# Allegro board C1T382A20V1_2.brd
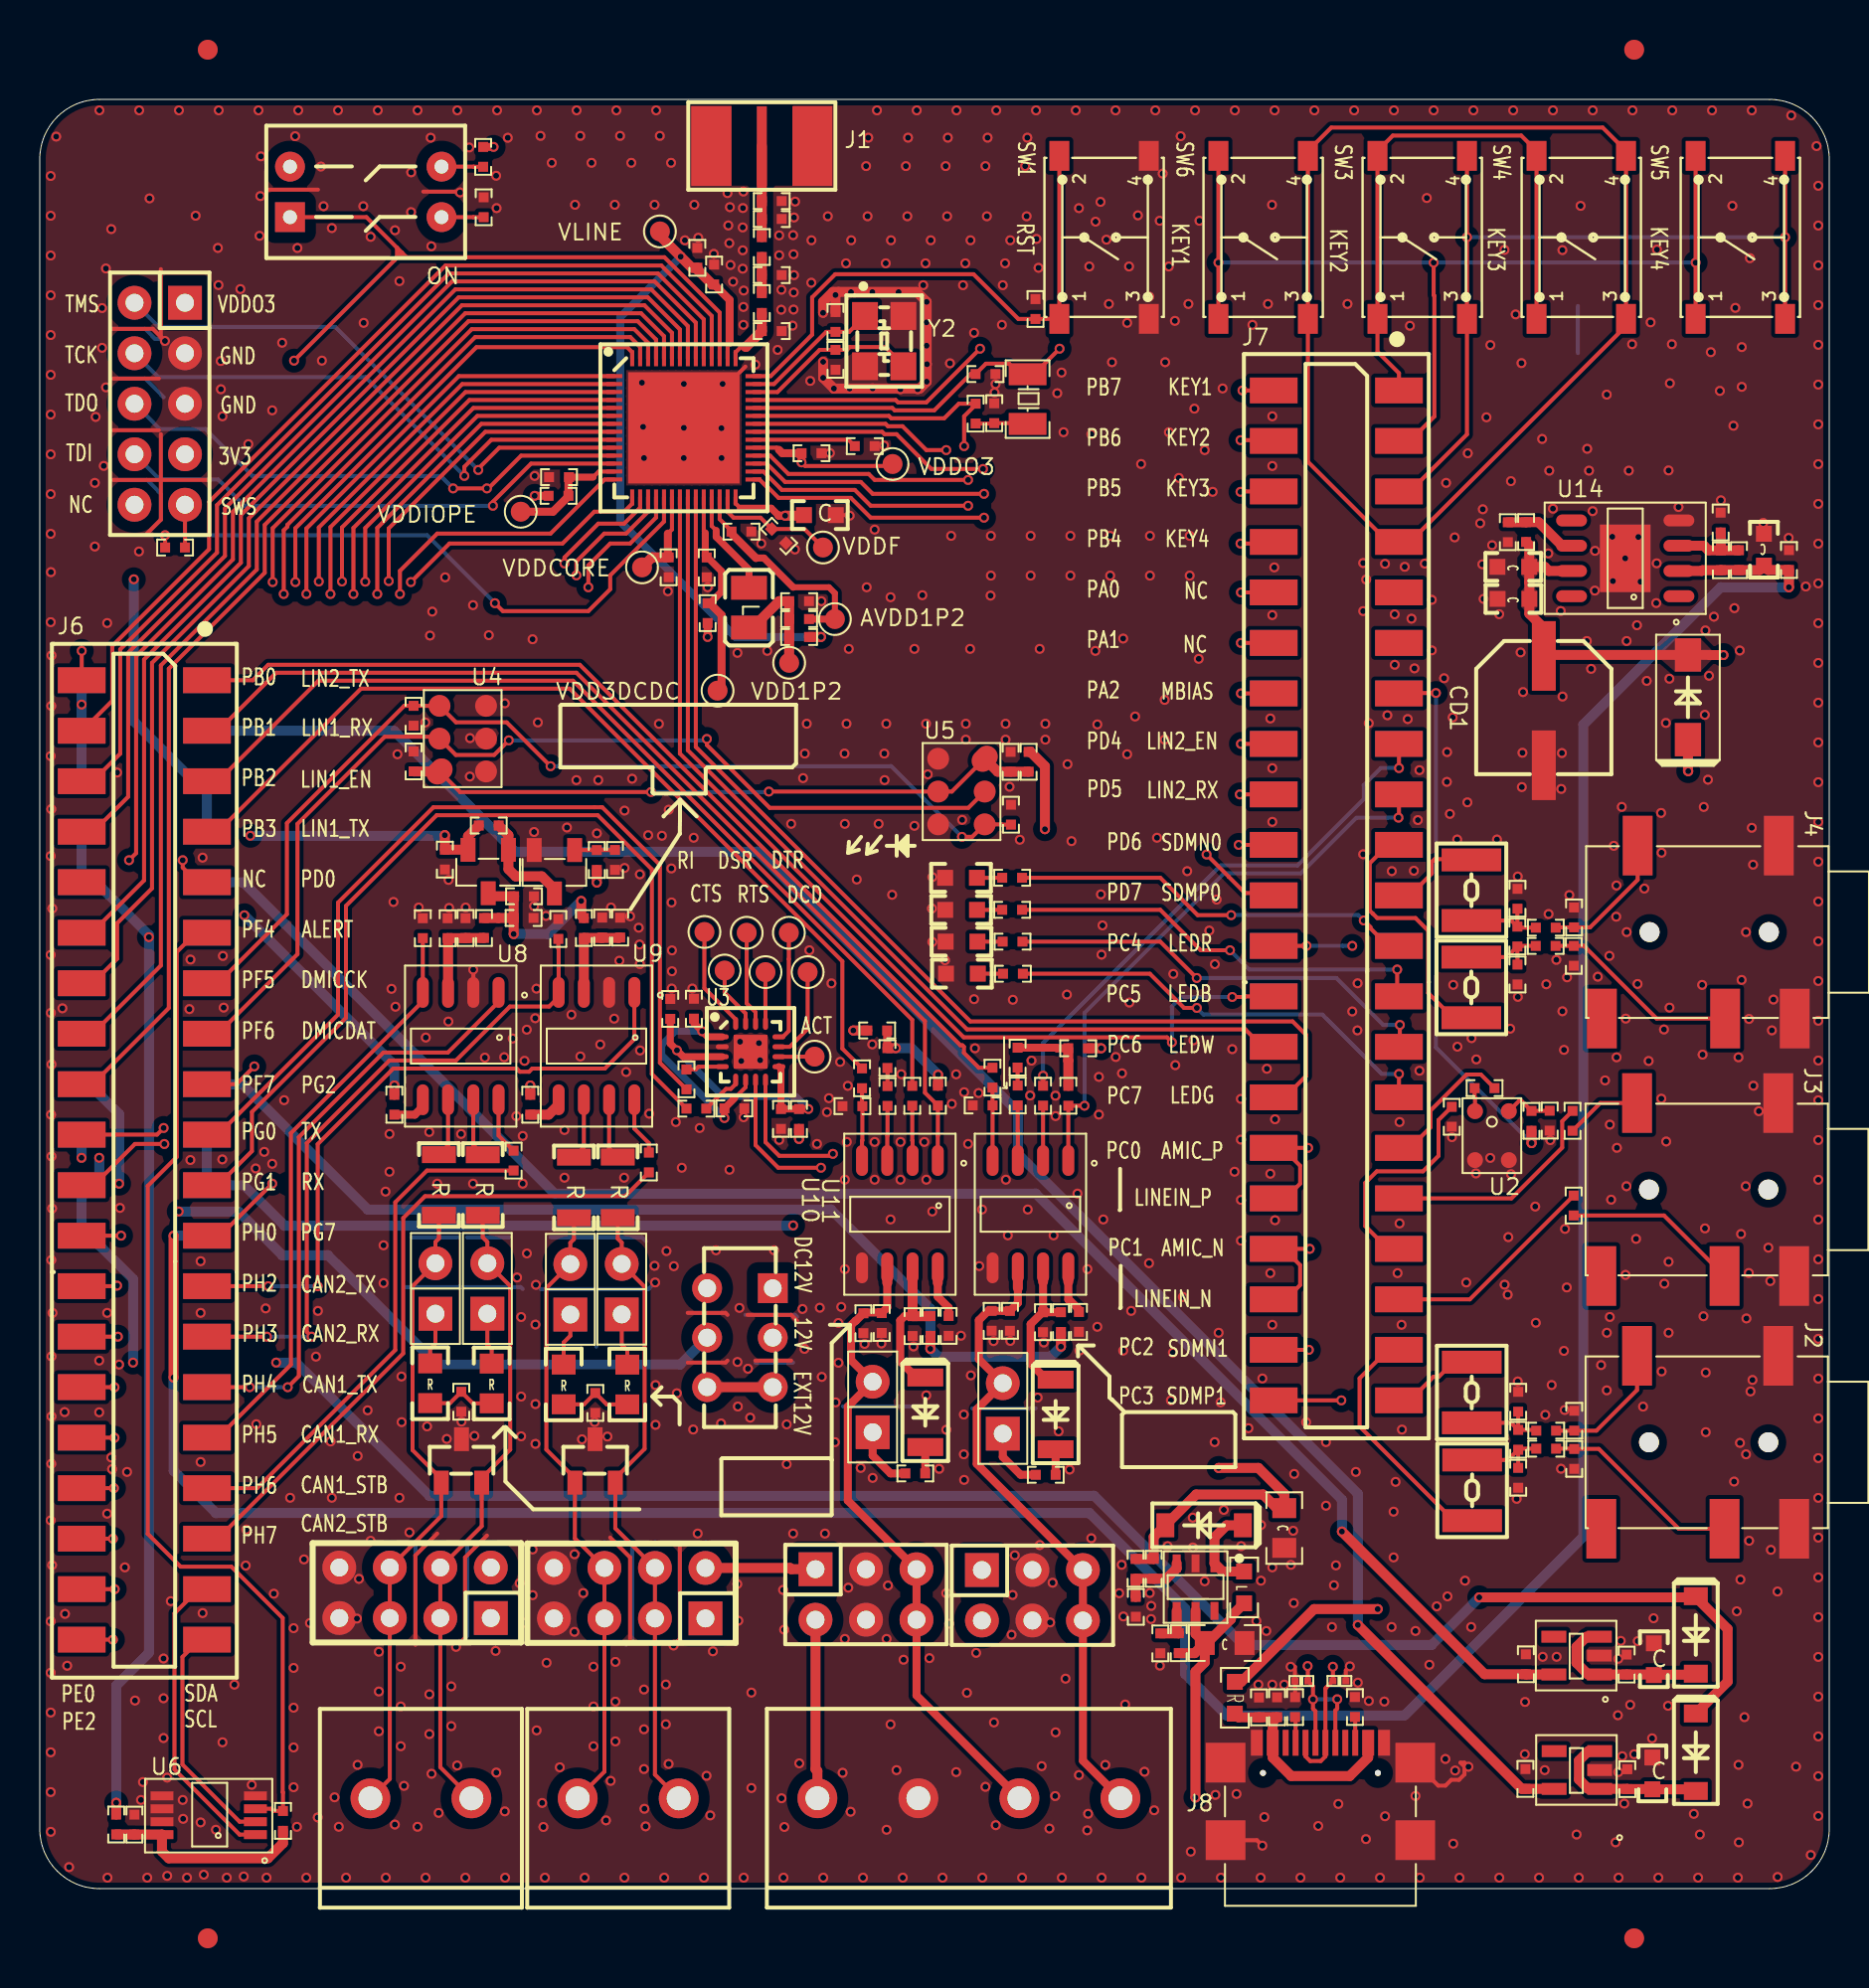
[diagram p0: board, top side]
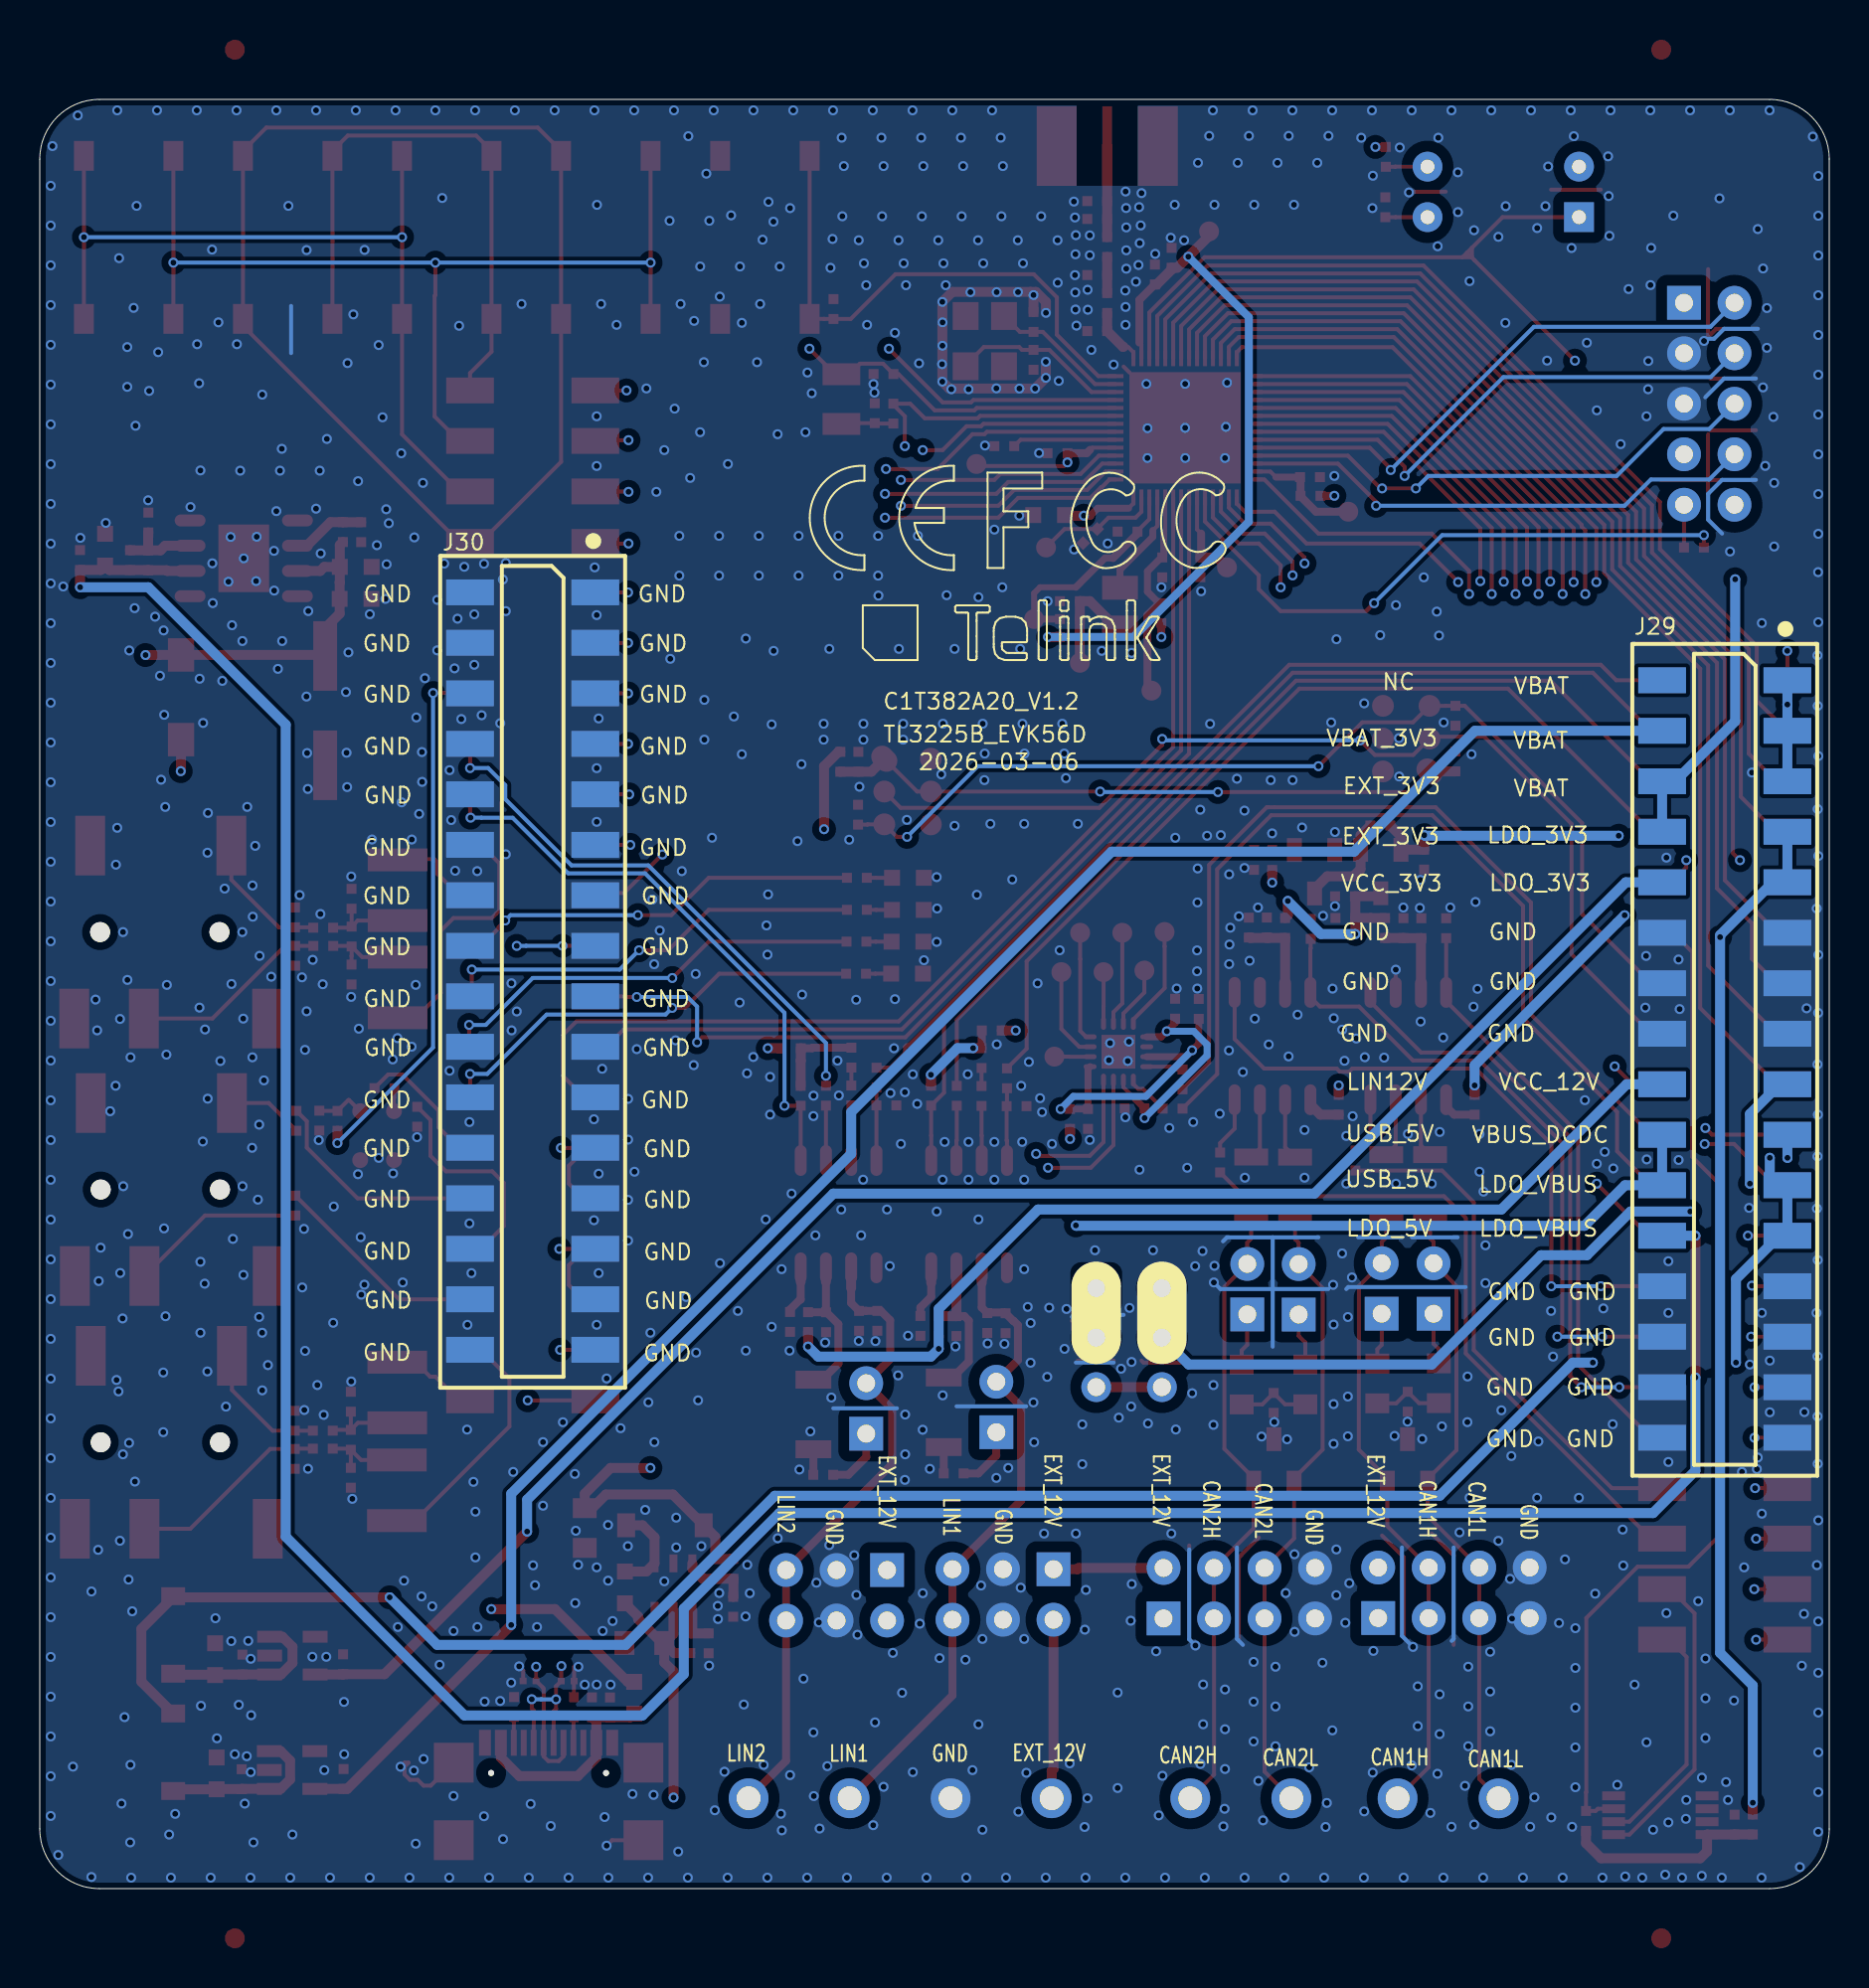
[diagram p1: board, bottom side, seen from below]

Outline 90 x 90 mm; copper layers: TOP, GND, POWER, BOTTOM. Coordinates in mm from the lower left corner of the outline.
Outline path: 0,87 arc(0.88,89.12) 3,90 87,90 arc(89.12,89.12) 90,87 90,3 arc(89.12,0.88) 87,0 3,0 arc(0.88,0.88) 0,3 0,87

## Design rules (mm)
constraint set DEFAULT: 

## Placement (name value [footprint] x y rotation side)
AVDD1P2  TP  [TP100]  39.99 63.86 0 top
C1  0.1uF  [0402]  33.92 81.19 90 top
C2  2.2uF  [0402]  33.07 82.03 90 top
C3  1.2pF  [0402]  36.81 78.35 0 top
C4  2.7pF  [0402]  36.81 81.16 0 top
C5  1.5pF  [0402]  36.81 83.98 0 top
C6  22pF  [0402]  47.56 76.19 180 top
C7  22pF  [0402]  48 74.22 270 top
C8  1uF  [0402]  50.08 79.45 90 top
C9  NC  [0402]  40.02 78.81 270 top
C10  1uF  [0402]  41.49 72.56 0 top
C11  NC  [0402]  40.02 76.9 270 top
C12  1uF  [0402]  38.81 72.2 0 top
C13  1uF  [0402]  26.12 71 180 top
C14  1uF  [0402]  37.17 68.04 315 top
C15  10uF  [0603C]  39.23 69.09 0 top
C16  4.7uF  [0402]  31.63 66.46 270 top
C17  1uF  [0402]  33.55 66.46 270 top
C18  1uF  [0402]  35.29 68.26 0 top
C19  NC  [0402]  74.36 20.67 90 top
C20  10pF  [0402]  77.17 21.62 90 top
C21  10nF  [0402]  72.67 40.27 0 top
C22  1uF  [0402]  75.94 38.63 270 top
C23  220nF  [0402]  74.36 22.57 90 top
C24  NC  [0402]  74.36 24.49 90 top
C25  10pF  [0402]  77.17 23.54 90 top
C26  1uF  [0402]  77.09 38.62 90 top
C27  NC  [0402]  74.32 45.98 90 top
C28  10pF  [0402]  77.16 46.92 90 top
C31  220nF  [0402]  74.32 47.89 90 top
C32  NC  [0402]  74.32 49.79 90 top
C33  10pF  [0402]  77.16 48.85 90 top
C35  0.1uF  [0402]  48.83 56.68 90 top
C36  0.1uF  [0402]  18.8 56.7 90 top
C37  0.1uF  [0402]  4.76 3.22 90 top
C38  0.1uF  [0402]  34.94 39.25 0 top
C39  4.7uF  [0402]  21.41 48.31 270 top
C40  0.1uF  [0402]  20.52 48.31 270 top
C43  NC  [0402]  19.27 48.31 270 top
C44  4.7uF  [0402]  29.19 48.34 270 top
C45  0.1uF  [0402]  28.28 48.34 270 top
C46  NC  [0402]  26.08 48.27 270 top
C47  4.7nF  [0402]  21.2 24.49 270 top
C48  10uF  [0402]  20.38 51.76 270 top
C49  10uF  [0402]  24.35 49.92 0 top
C50  4.7nF  [0402]  27.94 24.43 270 top
C51  0.1uF  [0402]  40.87 39.36 0 top
C52  100nF/25V  [0402]  43.89 28.3 90 top
C53  0.1uF  [0402]  47.42 39.39 0 top
C54  220pF  [0402]  48.79 28.56 90 top
C55  220pF  [0402]  42.34 28.45 90 top
C56  100nF/25V  [0402]  50.45 28.49 90 top
C57  NC  [0402]  56.02 16.09 270 top
C58  4.7uF/25V  [0805C]  62.59 18.14 270 top
C59  10uF  [0603C]  81.18 11.54 270 top
C60  1uF  [0402]  79.81 11.27 90 top
C61  1uF  [0402]  74.75 11.29 90 top
C62  4.7uF/25V  [0805C]  59.59 12.35 0 top
C63  1uF  [0402]  87.97 66.83 270 top
C64  4.7uF  [0603C]  86.72 67.35 90 top
C65  NC/1uF  [0402]  85.46 66.83 270 top
C66  4.7uF/25V  [0603C]  74.11 66.48 180 top
C67  10uF/25V  [0603C]  74.12 64.88 180 top
C68  1uF  [0402]  74.72 5.52 90 top
C69  10uF  [0603C]  81.11 5.79 270 top
C70  1uF  [0402]  79.84 5.51 90 top
C71  10uF  [0402]  61.32 9.12 90 top
C72  10uF  [0402]  38.19 64.76 0 top
C73  1uF  [0402]  77.14 34.36 90 top
C74  10nF  [0402]  71.02 38.83 90 top
C75  1uF  [0402]  37.28 38.72 270 top
C76  1uF  [0402]  32.9 44.26 90 top
C77  1uF  [0402]  31.71 44.25 90 top
CD1  100uF/35V  [VZH101M1VTR-0607]  75.64 59.25 90 top
D1  NC  [0201]  63.45 10.44 0 top
D2  NC  [0201]  65.36 10.45 180 top
D3  NC  [0402]  62.23 9.12 270 top
D4  Red  [0603-LED]  46.33 50.84 180 top
D5  Blue  [0603-LED]  46.34 49.23 180 top
D6  White  [0603-LED]  46.36 47.63 180 top
D7  Green  [0603-LED]  46.38 46.02 180 top
D8  PESD1CAN,215  [SOT-23]  21.21 21.51 0 top
D9  PESD1CAN,215  [SOT-23]  27.93 21.51 0 top
D10  4148  [SOD80]  44.54 23.96 270 top
D11  4148  [SOD80]  51.09 23.85 270 top
D12  NC  [0402]  41.42 28.44 90 top
D13  NC  [0402]  47.88 28.56 90 top
D14  LMBR0530T1G  [SOD-123]  58.56 18.27 0 top
D15  B340A  [DO-214AC]  82.89 59.92 270 top
D16  NC/TT0321  [0402]  36.81 84.88 180 top
D17  LMBR0530T1G  [SOD-123]  83.29 12.76 90 top
D18  LMBR0530T1G  [SOD-123]  83.29 6.86 90 top
J1  RFIN  [SMA-H]  36.31 87.66 270 top
J2  PJ327  [PJ-327]  89.94 22.45 270 top
J3  AIL1  [PJ-327]  89.94 35.16 270 top
J4  PJ327  [PJ-327]  89.97 48.11 270 top
J6  HEADER 20X2  [HDR2X20-2R54-SM-VM]  5.26 34.11 90 top
J7  HEADER 21x2  [HDR2X21-2R54-SM-M]  65.21 49.92 90 top
J8  Type-C 16pin  [TYPE_C_CQ_105PWB]  64.41 6.34 0 top
J9  JTAG  [HDR254F-2X5X850]  7.3 69.61 90 top
J10  DIP_2X2  [DIPSWITCH_2P54_7P62_2X2]  16.39 85.35 270 top
J15  CAN_Master_EN  [HDR254F-1X2X850]  22.51 31.46 270 top
J16  HEADER 4X2  [HDR254F-2X4X850]  12.52 13.61 0 top
J17  CON_5P08_1x2  [CON_5P08_1X2]  16.63 4.54 0 top
J18  CAN_Master_EN  [HDR254F-1X2X850]  19.9 31.46 270 top
J19  CAN_Master_EN  [HDR254F-1X2X850]  29.27 31.42 270 top
J20  HEADER 4X2  [HDR254F-2X4X850]  23.32 13.59 0 top
J21  CON_5P08_1x2  [CON_5P08_1X2]  27.05 4.54 0 top
J22  CAN_Master_EN  [HDR254F-1X2X850]  26.68 31.42 270 top
J23  can1  [HDR254F-1X2X850]  41.89 25.5 270 top
J24  can1  [HDR254F-1X2X850]  48.43 25.42 270 top
J25  HEADER 3X2  [HDR254F-2X3X850]  44.09 16.07 180 top
J27  HEADER 3X2  [HDR254F-2X3X850]  52.46 16.02 180 top
J29  HEADER 16X2  [HDR2X16-2R54-SM-M]  5.25 41.69 90 bottom
J30  HEADER 16X2  [HDR2X16-2R54-SM-M]  65.21 46.11 90 bottom
J31  4 HEADER  [CON_5P08_1X4]  44.19 4.54 0 top
L1  2.4nH  [0402]  36.31 79.76 90 top
L2  1.5nH  [0402]  36.31 82.57 90 top
L3  6.8uH  [1008L]  35.67 64.43 270 top
L4  150uH  [INDM3025X25]  72.04 20.04 90 top
L5  150uH  [INDM3025X25]  72.02 24.95 270 top
L6  150uH  [INDM3025X25]  72 45.33 90 top
L7  150uH  [INDM3025X25]  72 50.22 270 top
L8  4.7uH/CMH160808B4R7MT  [0603L]  60.57 15.15 270 top
NOREF  -  [unnamed]  8.45 92.5 0 top
NOREF#2  -  [unnamed]  80.19 -2.5 0 top
NOREF#3  -  [unnamed]  8.45 -2.5 0 top
NOREF#4  -  [unnamed]  80.19 92.5 0 top
Q1  PMOS_SI2301  [MOS_SOT-23]  22.55 51.16 180 top
Q2  SI2302  [MOS_SOT-23]  25.88 51.15 180 top
R2  10R  [0402]  47.07 74.19 90 top
R3  33  [0402R]  75.77 22.13 0 top
R4  2.2K  [0402]  75.03 38.62 90 top
R5  33  [0402R]  75.77 23.04 0 top
R7  33  [0402R]  75.74 47.42 0 top
R8  33  [0402R]  75.75 48.34 0 top
R9  100K  [0402]  18.8 59 90 top
R10  100K  [0402]  48.85 54.02 270 top
R12  NC  [0402]  12.23 3.4 270 top
R13  5.1K  [0402]  63.13 9.13 270 top
R14  5.1K  [0402]  66.14 9.13 270 top
R15  2R  [0603R]  60.1 9.6 270 top
R16  1K  [0402]  48.91 50.85 180 top
R17  1K  [0402]  48.91 49.23 180 top
R18  1K  [0402]  48.92 47.64 180 top
R19  1K  [0402]  48.95 46.02 180 top
R20  1K  [0402]  22.3 87.11 90 top
R21  1M  [0402]  22.32 84.58 90 top
R22  0  [0402]  23.83 36.62 270 top
R24  0  [0402]  30.63 36.52 270 top
R28  60.4R  [0805R]  22.73 25.41 270 top
R29  0R  [1206R]  22.28 35.39 270 top
R30  0R  [1206R]  20.07 35.39 270 top
R31  1K  [0402]  24.34 48.83 0 top
R32  60.4R  [0805R]  19.63 25.42 270 top
R33  1M  [0402]  22.58 53.47 0 top
R34  1M  [0402]  28.93 51.75 270 top
R35  60.4R  [0805R]  29.55 25.36 270 top
R36  0R  [1206R]  29.07 35.27 270 top
R37  0R  [1206R]  26.87 35.27 270 top
R38  60.4R  [0805R]  26.35 25.36 270 top
R39  10K  [0402]  45.17 39.89 270 top
R40  100K  [0402]  45.71 28.3 90 top
R41  10K  [0402]  51.73 39.88 270 top
R42  100K  [0402]  52.27 28.51 90 top
R43  0  [0402]  43.88 39.88 270 top
R44  0  [0402]  50.46 39.89 270 top
R45  33K  [0402]  42.64 39.87 270 top
R46  33K  [0402]  49.18 39.89 270 top
R47  1K  [0402]  41.35 40.76 270 top
R48  1K  [0402]  44.03 20.89 0 top
R49  1K  [0402]  47.91 40.79 270 top
R50  1K  [0402]  50.6 20.82 0 top
R51  3K  [0402]  42.63 41.78 90 top
R52  3K  [0402]  49.18 41.8 90 top
R53  300K_1%  [0402]  55.11 16.08 270 top
R54  100K  [0402]  57.28 12.34 90 top
R55  15K_1%  [0402]  55.12 14.18 270 top
R56  NC/100K  [0402]  56.36 12.34 270 top
R57  240K_1%  [0402]  84.55 66.81 90 top
R58  100K  [0402]  74.75 68.24 90 top
R59  32.4K_1%  [0402]  84.54 68.72 90 top
R60  100K  [0402]  73.84 68.23 270 top
R61  0R  [0402R]  49.73 56.68 270 top
R62  0R  [0402R]  38.19 38.72 270 top
R63  0R  [0402R]  3.84 3.22 270 top
R64  0R  [0402R]  17.84 39.43 270 top
R65  0R  [0402R]  42.12 43.16 0 top
R66  0R  [0402R]  28.02 51.74 90 top
R67  0R  [0402R]  24.67 39.43 270 top
R68  0R  [0402R]  22.34 48.32 270 top
R69  0R  [0402R]  27.37 48.32 270 top
R70  0R  [0402R]  52.22 42.27 180 top
R71  0R  [0402R]  44.8 28.3 90 top
R72  0R  [0402R]  51.36 28.5 90 top
R135  0R  [0402]  6.8 67.46 180 top
R136  0R  [0402]  33.02 39.23 180 top
R137  0R  [0402]  32.52 40.7 270 top
R138  0R  [0402]  38.19 63.86 0 top
R139  0R  [0402]  38.19 62.96 0 top
R140  0R  [0402]  26.09 70.06 0 top
R141  0R  [0402]  33.59 64.16 90 top
S1  SW_SL_DPDT  [SW-TH-6PIN-3_60X9_00-34NP]  35.21 27.71 90 top
SW1  SW4PIN_4.5x4.5  [SW_6X6_SMD]  53.53 83.06 90 top
SW3  SW4PIN_4.5x4.5  [SW_6X6_SMD]  69.53 83.06 90 top
SW4  SW4PIN_4.5x4.5  [SW_6X6_SMD]  77.53 83.06 90 top
SW5  SW4PIN_4.5x4.5  [SW_6X6_SMD]  85.53 83.06 90 top
SW6  SW4PIN_4.5x4.5  [SW_6X6_SMD]  61.53 83.06 90 top
TP4  TP  [TP100]  37.67 48.08 0 top
TP5  TP  [TP100]  38.62 46.1 0 top
TP6  TP  [TP100]  38.97 41.85 0 top
TP7  TP  [TP100]  35.55 48.08 0 top
TP8  TP  [TP100]  36.5 46.1 0 top
TP9  TP  [TP100]  34.45 46.18 0 top
TP10  TP  [TP100]  33.43 48.12 0 top
U1  TL3225B  [QFN_7X7_56PIN_0P4_5P60X5P60]  32.39 73.48 0 top
U2  WMM7037AT2  [GA_BFA423_A83]  73.03 37.88 0 top
U3  CH343P  [QFN_3X3_16PIN_0P5_1P70X1P70]  35.75 42.09 0 top
U4  WMM7047DTFN0  [DMIC_SPM0423HM4H-WB]  21.27 57.84 90 top
U5  WMM7047DTFN0  [DMIC_SPM0423HM4H-WB]  46.35 55.18 270 top
U6  P3T1750DP  [SOT505-1]  8.74 4.62 90 top
U8  TJA1462  [SOP8-1R27-7R40X5R50]  21.17 42.38 180 top
U9  TJA1462  [SOP8-1R27-7R40X5R50]  28 42.38 180 top
U10  TLIN1021A  [SOP8-1R27-7R40X5R50]  43.26 33.92 180 top
U11  TLIN1021A  [SOP8-1R27-7R40X5R50]  49.82 33.92 180 top
U12  CE1132_33M  [SOT-23-5]  77.3 11.72 90 top
U13  CE8441DJ  [SOT-23-6L_0P95]  58.13 15.16 180 top
U14  SA21345AFCA  [W25X10_20_40BL_GND]  79.74 66.92 90 top
U15  CE1132_33M  [SOT-23-5]  77.31 5.96 90 top
VDD1P2  TP  [TP100]  37.69 61.66 0 top
VDD3DCDC  TP  [TP100]  34.09 60.26 0 top
VDDCORE  TP  [TP100]  30.29 66.46 0 top
VDDF  TP  [TP100]  39.39 67.46 0 top
VDDIOPE  TP  [TP100]  24.19 69.26 0 top
VDDO3  TP  [TP100]  42.89 71.66 0 top
VLINE  TP  [TP100]  31.19 83.36 0 top
Y1  32.768KHz - 12.5pf - +/-10ppm  [OSC-ABS07]  49.68 74.92 270 top
Y2  24MHz-12pF-+/-10ppm  [OSCCC250X320X110]  42.47 77.84 0 top

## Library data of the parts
AVDD1P2 TP4-TP10 VDD1P2 VDD3DCDC VDDCORE VDDF VDDIOPE VDDO3 VLINE = TestPad100
C1-C5 C8-C14 C16-C19 C24 C27 C32 C38 C72 C75-C77 = C1005_NC
C6 C7 C59 C69 = C1608_NC
C15 C48 C49 C64 C66 C67 = C1608X5R0J106M
C20 C25 C28 C33 = C1005C0G1H100D
C21 C22 C26 C37 C39 C40 C43-C47 C50-C56 C63 C65 C71 C73 C74 = C1005X5R1C104K
C23 C31 = C1005X5R1C224M
C35 C36 = C1005X5R1C104K_1
C57 = C1005_NC_0
C58 C62 = C2012X5R1A475M
C60 C61 C68 C70 = C1608X5R0J106M_0
CD1 = TAJC476M016RNJ
D1 D2 = DIODE SCHOTTKY_0: Tolerance: RichardLC; User Part Number: pn
D3 D12 D13 D16 = DIODE SCHOTTKY_0
D4-D7 = 0603D_Green
D8 D9 = SM712_0
D10 = Diode_0
D11 = NC
D14 D17 D18 = Diode_CDBW0520L-G
D15 = Diode_B340A
J1 = SMA_JACK_2
J2-J4 = PJ327_2
J6 = HEADER 20X2: Tolerance: RichardLC
J7 = HEADER 21x2: Tolerance: RichardLC
J8 = Type-C 16pin_0
J9 = CONN PLUG 5x2: User Part Number: pn; Tolerance: RichardLC
J10 = HEADER 2X2_0: User Part Number: pn; Tolerance: RichardLC
J15 J18 J19 J22 = B2S_0: User Part Number: pn; Tolerance: RichardLC
J16 J20 = HEADER 4X2: User Part Number: pn; Tolerance: RichardLC
J17 J21 = CON_2.54mm_1x2: User Part Number: pn
J23 J24 = HEADER 1x2_8: User Part Number: pn; Tolerance: RichardLC
J25 J27 = HEADER 3X2: Tolerance: RichardLC; User Part Number: pn
J29 J30 = HEADER 16X2: Tolerance: RichardLC
J31 = 4 HEADER: User Part Number: pn
L1 L2 = MLK1608_000R
L3 = IND_0
L4-L7 = IND_150uH_3025
L8 = MLK1005_NC
Q1 = PMOS_SI2301
Q2 = NMOS_SI2302
R2 = RS0603K102JT
R3 R5 R7 R8 R61-R72 = RS0402K330JT
R4 R9 R10 R12 R20-R22 R24 R39-R52 R54 R56 R58 R60 R135 = RS0402K104JT
R13-R15 = RS0402K330JT: room: USB
R16-R19 = RS0402K101JT
R28 R31 R32 R35 R38 R136 R137 = RS0402K102JT
R29 R30 R36 R37 = RS1206_NC: User Part Number: pn; Tolerance: RichardLC
R33 R34 R138-R141 = RS0402K105JT
R53 R55 = RS0402_NC_0
R57 R59 = RS0402_NC
S1 = SW_SL_DPDT: User Part Number: pn; Tolerance: RichardLC
SW1 SW3-SW6 = SW_6X6_SMD_0
U1 = TL3225B_QFN56: Tolerance: RichardLC
U2 = MULPS4CX-RM5_0
U3 = CH343P
U4 = LD1117/SO_0
U5 = LD1117/SO_1
U6 = P3T1750DP: Tolerance: RichardLC
U8 U9 = TJA1462: Tolerance: RichardLC
U10 = TLIN1021A: Tolerance: RichardLC
U11 = CA-IF1021: Tolerance: RichardLC
U12 U15 = CE1132_3V3_SOT-23-5
U13 = TPS61070_ADJ_SOT-23-6_0
U14 = SiT5356AI-FQ-33N0-12_2.000000: Tolerance: RichardLC
Y1 = OSC_2x6_2pin_16Mhz
Y2 = CRYSTAL4/SM_0: Tolerance: RichardLC

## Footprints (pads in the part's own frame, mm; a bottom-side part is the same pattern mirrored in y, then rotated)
0201
  rect 0.35x0.33 smd: 1(-0.325,0) 2(0.325,0)
0402
  rect 0.5x0.5 smd: 1(-0.5,0) 2(0.5,0)
0402R
  rect 0.5x0.5 smd: 1(-0.5,0) 2(0.5,0)
0603-LED
  rect 0.8x0.8 smd: A(-0.8,0) C(0.8,0)
0603C
  rect 0.8x0.8 smd: 1(-0.8,0) 2(0.8,0)
0603L
  rect 0.8x0.8 smd: 1(-0.8,0) 2(0.8,0)
0603R
  rect 0.8x0.8 smd: 1(-0.8,0) 2(0.8,0)
0805C
  rect 1x1.2 smd: 1(-1,0) 2(1,0)
0805R
  rect 1x1.2 smd: 1(-1,0) 2(1,0)
1008L
  rect 1.2x1.8 smd: 1(-1,0) 2(1,0)
1206R
  rect 0.85x1.7 smd: 1(-1.525,0) 2(1.525,0)
CON_5P08_1X2
  round 2 hole 1.2: 1(0,0) 2(5.08,0)
CON_5P08_1X4
  round 2 hole 1.2: 1(10.16,0) 2(5.08,0) 3(0,0) 4(-5.08,0)
DIPSWITCH_2P54_7P62_2X2
  rect 1.5x1.5 hole 0.7: 1(1.27,-3.81)
  round 1.5 hole 0.7: 2(1.27,3.81) 3(-1.27,-3.81) 4(-1.27,3.81)
DMIC_SPM0423HM4H-WB
  round 1.1 smd: 1(-1.65,-1.17) 2(0,-1.17) 3(1.65,-1.17) 4(1.65,1.17) 5(0,1.17)
  oval 1.4x1.1 smd rot 135: 6(-1.65,1.17)
DO-214AC
  rect 1.68x1.32 smd: A(2.13,0) C(-2.13,0)
GA_BFA423_A83
  round 0.8 smd: 1(-0.85,1.23) 2(-0.85,-1.23) 3(0.85,-1.23) 4(0.85,1.23)
HDR2X16-2R54-SM-M
  rect 1.3x2.4 smd: 1(19.09,-3.15) 2(19.09,3.15) 3(16.55,-3.15) 4(16.55,3.15) 5(14.01,-3.15) 6(14.01,3.15) 7(11.47,-3.15) 8(11.47,3.15) 9(8.93,-3.15) 10(8.93,3.15) 11(6.39,-3.15) 12(6.39,3.15) 13(3.85,-3.15) 14(3.85,3.15) 15(1.31,-3.15) 16(1.31,3.15) 17(-1.23,-3.15) 18(-1.23,3.15) 19(-3.77,-3.15) 20(-3.77,3.15) 21(-6.31,-3.15) 22(-6.31,3.15) 23(-8.85,-3.15) 24(-8.85,3.15) 25(-11.39,-3.15) 26(-11.39,3.15) 27(-13.93,-3.15) 28(-13.93,3.15) 29(-16.47,-3.15) 30(-16.47,3.15) 31(-19.01,-3.15) 32(-19.01,3.15)
HDR2X20-2R54-SM-VM
  rect 1.3x2.4 smd: 1(26.67,-3.15) 2(26.67,3.15) 3(24.13,-3.15) 4(24.13,3.15) 5(21.59,-3.15) 6(21.59,3.15) 7(19.05,-3.15) 8(19.05,3.15) 9(16.51,-3.15) 10(16.51,3.15) 11(13.97,-3.15) 12(13.97,3.15) 13(11.43,-3.15) 14(11.43,3.15) 15(8.89,-3.15) 16(8.89,3.15) 17(6.35,-3.15) 18(6.35,3.15) 19(3.81,-3.15) 20(3.81,3.15) 21(1.27,-3.15) 22(1.27,3.15) 23(-1.27,-3.15) 24(-1.27,3.15) 25(-3.81,-3.15) 26(-3.81,3.15) 27(-6.35,-3.15) 28(-6.35,3.15) 29(-8.89,-3.15) 30(-8.89,3.15) 31(-11.43,-3.15) 32(-11.43,3.15) 33(-13.97,-3.15) 34(-13.97,3.15) 35(-16.51,-3.15) 36(-16.51,3.15) 37(-19.05,-3.15) 38(-19.05,3.15) 39(-21.59,-3.15) 40(-21.59,3.15)
HDR2X21-2R54-SM-M
  rect 1.3x2.4 smd: 1(25.44,-3.15) 2(25.44,3.15) 3(22.9,-3.15) 4(22.9,3.15) 5(20.36,-3.15) 6(20.36,3.15) 7(17.82,-3.15) 8(17.82,3.15) 9(15.28,-3.15) 10(15.28,3.15) 11(12.74,-3.15) 12(12.74,3.15) 13(10.2,-3.15) 14(10.2,3.15) 15(7.66,-3.15) 16(7.66,3.15) 17(5.12,-3.15) 18(5.12,3.15) 19(2.58,-3.15) 20(2.58,3.15) 21(0.04,-3.15) 22(0.04,3.15) 23(-2.5,-3.15) 24(-2.5,3.15) 25(-5.04,-3.15) 26(-5.04,3.15) 27(-7.58,-3.15) 28(-7.58,3.15) 29(-10.12,-3.15) 30(-10.12,3.15) 31(-12.66,-3.15) 32(-12.66,3.15) 33(-15.2,-3.15) 34(-15.2,3.15) 35(-17.74,-3.15) 36(-17.74,3.15) 37(-20.28,-3.15) 38(-20.28,3.15) 39(-22.82,-3.15) 40(-22.82,3.15) 41(-25.36,-3.15) 42(-25.36,3.15)
HDR254F-1X2X850
  rect 1.7x1.7 hole 0.9: 1(2.54,0)
  round 1.7 hole 0.9: 2(0,0)
HDR254F-2X3X850
  rect 1.7x1.7 hole 0.9: 1(5.08,0)
  round 1.7 hole 0.9: 2(5.08,2.54) 3(2.54,0) 4(2.54,2.54) 5(0,0) 6(0,2.54)
HDR254F-2X4X850
  rect 1.7x1.7 hole 0.9: 1(10.16,0)
  round 1.7 hole 0.9: 2(10.16,2.54) 3(7.62,0) 4(7.62,2.54) 5(5.08,0) 6(5.08,2.54) 7(2.54,0) 8(2.54,2.54)
HDR254F-2X5X850
  rect 1.7x1.7 hole 0.9: 1(10.16,0)
  round 1.7 hole 0.9: 2(10.16,2.54) 3(7.62,0) 4(7.62,2.54) 5(5.08,0) 6(5.08,2.54) 7(2.54,0) 8(2.54,2.54) 9(0,0) 10(0,2.54)
INDM3025X25
  rect 1.15x3 smd: 1(-1.525,0) 2(1.525,0)
MOS_SOT-23
  rect 0.75x1.2 smd: 1(-1.016,-1.092) 2(1.016,-1.092) 3(0,1.092)
OSC-ABS07
  rect 1.1x1.9 smd: 1(-1.25,0) 2(1.25,0)
OSCCC250X320X110
  rect 1.3x1.4 smd: 1(-0.965,1.265) 2(-0.965,-1.265) 3(0.965,-1.265) 4(0.965,1.265)
PJ-327
  round 1 hole 1 unplated: (0,-3) (0,-9)
  rect 3x1.5 smd: 1(-4.35,-2.5) 2(4.35,-5.2) 3(-4.35,-9.6) 4(4.35,-11.4) 5(4.35,-1.7)
QFN_3X3_16PIN_0P5_1P70X1P70
  oval 0.65x0.25 smd: 1(-1.425,0.75) 2(-1.425,0.25) 3(-1.425,-0.25) 4(-1.425,-0.75) 9(1.425,-0.75) 10(1.425,-0.25) 11(1.425,0.25) 12(1.425,0.75)
  oval 0.25x0.65 smd: 5(-0.75,-1.425) 6(-0.25,-1.425) 7(0.25,-1.425) 8(0.75,-1.425) 13(0.75,1.425) 14(0.25,1.425) 15(-0.25,1.425) 16(-0.75,1.425)
  rect 1.7x1.7 smd: 17(0,0)
QFN_7X7_56PIN_0P4_5P60X5P60
  rect 0.8x0.2 smd: 1(-3.5,2.6) 2(-3.5,2.2) 3(-3.5,1.8) 4(-3.5,1.4) 5(-3.5,1) 6(-3.5,0.6) 7(-3.5,0.2) 8(-3.5,-0.2) 9(-3.5,-0.6) 10(-3.5,-1) 11(-3.5,-1.4) 12(-3.5,-1.8) 13(-3.5,-2.2) 14(-3.5,-2.6) 29(3.5,-2.6) 30(3.5,-2.2) 31(3.5,-1.8) 32(3.5,-1.4) 33(3.5,-1) 34(3.5,-0.6) 35(3.5,-0.2) 36(3.5,0.2) 37(3.5,0.6) 38(3.5,1) 39(3.5,1.4) 40(3.5,1.8) 41(3.5,2.2) 42(3.5,2.6)
  rect 0.2x0.8 smd: 15(-2.6,-3.5) 16(-2.2,-3.5) 17(-1.8,-3.5) 18(-1.4,-3.5) 19(-1,-3.5) 20(-0.6,-3.5) 21(-0.2,-3.5) 22(0.2,-3.5) 23(0.6,-3.5) 24(1,-3.5) 25(1.4,-3.5) 26(1.8,-3.5) 27(2.2,-3.5) 28(2.6,-3.5) 43(2.6,3.5) 44(2.2,3.5) 45(1.8,3.5) 46(1.4,3.5) 47(1,3.5) 48(0.6,3.5) 49(0.2,3.5) 50(-0.2,3.5) 51(-0.6,3.5) 52(-1,3.5) 53(-1.4,3.5) 54(-1.8,3.5) 55(-2.2,3.5) 56(-2.6,3.5)
  rect 5.6x5.6 smd: 57(0,0)
SMA-H
  rect 4x0.5 smd: 1(0,0)
  rect 4x2 smd: 2(0,-2.54) 3(0,2.54) 4(0,-2.54) 5(0,2.54)
SOD80
  rect 0.9x1.8 smd: A(-1.75,0) C(1.75,0)
SOD-123
  rect 0.9x1.2 smd: A(1.95,0) C(-1.95,0)
SOP8-1R27-7R40X5R50
  oval 0.6x1.55 smd: 1(-1.905,-2.7) 2(-0.635,-2.7) 3(0.635,-2.7) 4(1.905,-2.7) 5(1.905,2.7) 6(0.635,2.7) 7(-0.635,2.7) 8(-1.905,2.7)
SOT505-1
  rect 0.45x1.15 smd: 1(-1.905,-2.1) 2(-1.255,-2.1) 3(-0.605,-2.1) 4(0.045,-2.1) 5(0.045,2.6) 6(-0.605,2.6) 7(-1.255,2.6) 8(-1.905,2.6)
SOT-23
  rect 0.75x1.2 smd: 1(-1.016,-1.092) 2(1.016,-1.092) 3(0,1.092)
SOT-23-5
  rect 0.6x1.25 smd: 1(-0.95,-1.145) 2(0,-1.145) 3(0.95,-1.145) 4(0.95,1.145) 5(-0.95,1.145)
SOT-23-6L_0P95
  rect 0.4x0.9 smd: 1(-0.95,-1.195) 2(0,-1.195) 3(0.95,-1.195) 4(0.95,1.195) 5(0,1.195) 6(-0.95,1.195)
SW-TH-6PIN-3_60X9_00-34NP
  rect 1.499x1.499 hole 0.889: 1(2.489,-1.651)
  round 1.5 hole 0.9: 2(0,-1.651) 3(-2.489,-1.651) 4(-2.489,1.651) 5(0,1.651) 6(2.489,1.651)
SW_6X6_SMD
  rect 1.5x1 smd: 1(-4.1,2.25) 2(4.1,2.25) 3(-4.1,-2.25) 4(4.1,-2.25)
TP100
  round 1.001 smd: 1(0,0)
TYPE_C_CQ_105PWB
  round 0.3 hole 0.7 unplated: (-2.89,-0.52) (2.89,-0.52)
  rect 2x2 smd: 13(-4.77,0) 14(4.77,0) 15(-4.77,-3.9) 16(4.77,-3.9)
  rect 0.6x1.3 smd: A1B12(-3.2,1) A4B9(-2.4,1) B1A12(3.2,1) B4A9(2.4,1)
  rect 0.3x1.3 smd: A5(-1.25,1) A6(-0.25,1) A7(0.25,1) A8(1.25,1) B5(1.75,1) B6(0.75,1) B7(-0.75,1) B8(-1.75,1)
unnamed
  round 1 smd: 1(0,0)
VZH101M1VTR-0607
  rect 3.5x1.2 smd: 1(2.75,0) 2(-2.75,0)
W25X10_20_40BL_GND
  oval 0.6x1.55 smd: 1(-1.905,-2.7) 2(-0.635,-2.7) 3(0.635,-2.7) 4(1.905,-2.7) 5(1.905,2.7) 6(0.635,2.7) 7(-0.635,2.7) 8(-1.905,2.7)
  rect 3.4x2.55 smd: 9(0,0)

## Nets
12V: J29.17 S1.2 S1.5
GND: C1.2 C2.2 C3.2 C4.2 C5.2 C6.1 C7.1 C8.2 C9.1 C10.2 C11.2 C12.2 C13.2 C14.2 C15.2 C16.2 C17.2 C18.2 C19.1 C20.1 C22.2 C24.2 C25.2 C27.1 C28.1 C32.2 C33.2 C35.2 C36.2 C37.2 C38.2 C39.1 C40.1 C43.1 C44.1 C45.1 C46.1 C47.2 C48.2 C49.2 C50.2 C51.1 C52.1 C53.1 C54.1 C55.1 C56.1 C58.2 C59.1 C60.2 C61.2 C62.2 C63.1 C64.2 C66.2 C67.2 C68.2 C69.1 C70.2 C71.2 C72.2 C74.1 C75.2 C76.2 C77.2 CD1.2 D1.1 D2.1 D3.1 D4.C(CATHODE) D5.C(CATHODE) D6.C(CATHODE) D7.C(CATHODE) D8.3 D9.3 D12.1 D13.1 D16.1 J1.2 J1.3 J1.4 J1.5 J2.1 J2.5 J3.1 J3.5 J4.1 J4.5 J8.13 J8.14 J8.15 J8.16 J8.A1B12 J8.B1A12 J9.3 J9.5 J16.7 J16.8 J20.7 J20.8 J25.3 J25.4 J27.3 J27.4 J29.11 J29.12 J29.13 J29.14 J29.15 J29.16 J29.25 J29.26 J29.27 J29.28 J29.29 J29.30 J29.31 J29.32 J30.1 J30.2 J30.3 J30.4 J30.5 J30.6 J30.7 J30.8 J30.9 J30.10 J30.11 J30.12 J30.13 J30.14 J30.15 J30.16 J30.17 J30.18 J30.19 J30.20 J30.21 J30.22 J30.23 J30.24 J30.25 J30.26 J30.27 J30.28 J30.29 J30.30 J30.31 J30.32 J31.3 Q2.2(S) R9.1 R10.1 R13.1 R14.1 R21.2 R31.2 R34.2 R40.1 R42.1 R55.2 R56.2 R59.2 R60.2 SW1.3 SW1.4 U1.57 U2.2 U2.3 U3.2 U3.17 U4.1 U4.2(SE) U4.3 U5.1 U5.3 U6.4 U6.5 U6.6 U6.7 U8.2 U9.2 U10.5 U11.5 U12.2(VSS) U13.2 U14.4 U14.9 U15.2(VSS) Y2.2 Y2.4
V3: C38.1 C76.1 U3.1(VIO) U3.6
VBAT_3V3: C68.1 J29.4 U15.5
VBUS_DCDC: C62.1 J29.19 L8.2 R54.1 U13.5(VIN)
VCC_3V3: C61.1 J29.10 U12.5
VCC_12V: C66.1 C67.1 CD1.1 D15.C R58.1 S1.3 S1.4 U14.7
VDD_DMIC: C35.1 C36.1 R61.2 U4.6 U5.2(SE) U5.6
VDDF: C14.1 U1.27 VDDF.1(TP)
AIN_LINEIN_N: C73.2 J7.37
AIN_LINEIN_P: C26.2 J7.33
AIN_MIC_N: C74.2 J7.35
AIN_MIC_P: C21.2 J7.31
CAN1_3V3: R64.2 U8.5(VIO)
CAN1_5V: C39.2 C40.2 R68.2 U8.3
CAN2_3V3: R67.2 U9.5(VIO)
CAN2_5V: C44.2 C45.2 R69.2 U9.3
CAN_5V: C49.1 Q1.3 R31.1 R68.1 R69.1
CAN_CANH: R29.1 U8.7
CAN_CANH2: R36.1 U9.7
CAN_CANL: R30.1 U8.6
CAN_CANL2: R37.1 U9.6
CANH: D8.2 J15.2 J16.3 J16.4 J17.2 R29.2
CANH2: D9.2 J19.2 J20.3 J20.4 J21.2 R36.2
CANL: D8.1 J16.5 J16.6 J17.1 J18.2 R30.2
CANL2: D9.1 J20.5 J20.6 J21.1 J22.2 R37.2
DCDC_12V: C57.1 C58.1 D14.C R53.1 S1.1 S1.6
DM2: D2.2(CATHODE) J8.A7 J8.B7 U3.8
DMICCK: J6.13 R9.2 R10.2 U4.4 U5.4
DMICDAT: J6.15 U4.5 U5.5
DP2: D1.2(CATHODE) J8.A6 J8.B6 U3.7
EXT_3V3: J9.7 J29.6 J29.8
EXT_12V: D15.A J16.1 J16.2 J20.1 J20.2 J25.1 J25.2 J27.1 J27.2 J31.4
I3C_3V3: C37.1 R12.2 R63.2 U6.8(VCC)
I3C_ALERT: J6.11 R12.1 U6.3
I3C_SCL: J6.39 U6.2
I3C_SDA: J6.37 U6.1
LDO_3V3: J29.7 J29.9 R61.1 R63.1 R64.1 R65.1 R66.1 R67.1 R70.1
LDO_5V: C63.2 C64.1 C65.2 J29.24 R57.1 U14.2(OUT)
LDO_VBUS: C48.1 D17.A D18.A J29.21 J29.23 Q1.2(S) R33.1
LED_B: J7.25 R17.1
LED_G: J7.29 R19.1
LED_R: J7.23 R16.1
LED_W: J7.27 R18.1
LIN1_3V3: R39.1 R51.2 R65.2
LIN1_12V: C52.2 D10.A R71.2 U10.7
LIN2_3V3: R41.1 R52.2 R70.2
LIN2_12V: C56.2 D11.A R72.2 U11.7
LIN_12V: J29.18 R71.1 R72.1
LIN_EN1: J6.5 R43.1
LIN_EN2: J7.15 R44.1
LIN_LIN1: C55.2 D12.2(CATHODE) J23.2 J25.5 J25.6 J31.2 U10.6
LIN_LIN2: C54.2 D13.2(CATHODE) J24.2 J27.5 J27.6 J31.1 U11.6
LIN_RXD1: J6.3 R39.2 U10.1
LIN_RXD2: J7.17 R41.2 U11.1
LIN_TXD1: J6.7 R47.1
LIN_TXD2: J6.1 R49.1
TL_ANT: C3.1 L1.1 U1.43
TL_AVDD1P2: AVDD1P2.1(TP) C18.1 R138.2 U1.26
TL_CAN_RXD: C43.2 J6.31 U8.4
TL_CAN_RXD2: C46.2 J6.27 U9.4
TL_CAN_STB: J6.33 R22.2
TL_CAN_STB2: J6.35 R24.2
TL_CAN_TXD: J6.29 U8.1
TL_CAN_TXD2: J6.25 U9.1
TL_KEY1: J7.1 SW3.1 SW3.2 SW4.1 SW4.2
TL_KEY2: J7.3 SW5.1 SW5.2 SW6.1 SW6.2
TL_KEY3: J7.5 SW3.3 SW3.4 SW5.3 SW5.4
TL_KEY4: J7.7 SW4.3 SW4.4 SW6.3 SW6.4
TL_MICBIAS: J7.13 R4.1
TL_PA0: J7.10 U1.16
TL_PA1: J7.12 U1.17
TL_PA2: J7.14 U1.18
TL_PA7: R135.2 U1.19
TL_PB0: J6.2 J10.1 J10.3 U1.45
TL_PB1: J6.4 U1.46
TL_PB2: J6.6 U1.47
TL_PB3: J6.8 U1.48
TL_PB4: J7.8 U1.29
TL_PB5: J7.6 U1.30
TL_PB6: J7.4 U1.31
TL_PB7: J7.2 U1.32
TL_PC0: J7.32 J7.34 U1.35
TL_PC1: J7.36 J7.38 U1.36
TL_PC2: J7.40 R2.2 U1.37
TL_PC3: C6.2 J7.42 U1.38 Y1.1
TL_PC4: J7.24 U1.39
TL_PC5: J7.26 U1.21
TL_PC6: J7.28 U1.22
TL_PC7: J7.30 U1.23
TL_PD0: J6.9 U1.49
TL_PD4: J7.16 J9.8 U1.12
TL_PD5: J7.18 J9.6 U1.11
TL_PD6: J7.20 J9.2 U1.10
TL_PD7: J7.22 J9.4 U1.9
TL_PE0: J6.38 U1.14
TL_PE2: J6.40 U1.15
TL_PF4: J6.12 U1.50
TL_PF5: J6.14 U1.51
TL_PF6: J6.16 U1.52
TL_PF7: J6.18 U1.53
TL_PG0: J6.20 U1.54
TL_PG1: J6.22 U1.55
TL_PG2: J6.17 U1.56
TL_PG7: J6.23 U1.1
TL_PH0: J6.24 U1.2
TL_PH2: J6.26 U1.3
TL_PH3: J6.28 U1.4
TL_PH4: J6.30 U1.5
TL_PH5: J6.32 U1.6
TL_PH6: J6.34 U1.7
TL_PH7: J6.36 U1.8
TL_RF: C5.1 D16.2(CATHODE) J1.1 L2.2
TL_RST: C8.1 SW1.1 SW1.2 U1.42
TL_SDMN0: J7.19 L6.1
TL_SDMN1: J7.39 L4.1
TL_SDMP0: J7.21 L7.1
TL_SDMP1: J7.41 L5.1
TL_VBAT: C15.1 J29.1 J29.3 J29.5 U1.28
TL_VDD1P2: C72.1 L3.2 R138.1 R139.1 VDD1P2.1(TP)
TL_VDD3DCDC: C17.1 R141.2 U1.24 VDD3DCDC.1(TP)
TL_VDDCORE: C16.1 U1.20 VDDCORE.1(TP)
TL_VDDIOPE: C13.1 R140.2 U1.13 VDDIOPE.1(TP)
TL_VDDO3: C12.1 J9.1(9) R20.2 R140.1 R141.1 U1.33 VDDO3.1(TP)
TL_VLINE: C1.1 C2.1 R139.2 U1.44 VLINE.1(TP)
TL_XC1: C11.1 U1.40 Y2.3
TL_XC2: C9.2 U1.41(XC2) Y2.1
UART_5V: C75.1 C77.1 R62.1 U3.3 U3.9
UART_RX: J6.21 R136.2
UART_TX: J6.19 R137.2
USB_5V: J29.20 J29.22 R15.1 R62.2
USB_VBUSU: C71.1 D3.2(CATHODE) J8.A4B9 J8.B4A9(VBUS#B4A9) R15.2
N20253886: C22.1 R4.2 U2.4(VDD)
N20253935: C21.1 U2.1
N20253959: C26.1 J3.3
N20337202: C19.2 C23.1 L4.2 R3.1
N20337204: C20.2 J2.2 R3.2
N20337251: C23.2 C24.1 L5.2 R5.1
N20337259: C25.1 J2.3 R5.2
N20337346: C27.2 C31.1 L6.2 R7.1
N20337363: C28.2 J4.2 R7.2
N20337410: C31.2 C32.1 L7.2 R8.1
N20337418: C33.1 J4.3 R8.2
N20392329: D4.A R16.2
N20392898: D5.A R17.2
N20393445: D6.A R18.2
N20393873: D7.A R19.2
N20432643: C4.1 L1.2 L2.1
N20432803: C7.2 R2.1 Y1.2
N20433121: C10.1 U1.34
N20433225: L3.1 U1.25
N20446669: D14.A L8.1 U13.1
N20446778: C59.2 C60.1 D17.C U12.1 U12.3
N20446804: C57.2 R53.2 R55.1 U13.3
N20446808: R54.2 R56.1 U13.4
N20447279: C65.1 R57.2 R59.1 U14.3
N20447283: R58.2 R60.1 U14.6
N20449113: J8.A5 R13.2
N20449208: J8.B5 R14.2
N20451817: J15.1 R28.1
N20451819: C47.1 R28.2 R32.2
N20451956: J18.1 R32.1
N20451988: J19.1 R35.1
N20451990: C50.1 R35.2 R38.2
N20452190: J22.1 R38.1
N20458083: R22.1 U8.8
N20458950: Q1.1 Q2.3 R33.2
N20458968: Q2.1 R34.1 R66.2
N20459724: R40.2 U10.8
N20459777: R45.2 U10.3(WAKE)
N20459821: R46.2 U11.3(WAKE_N)
N20459876: C51.2 R47.2 U10.4
N20459892: D10.C R48.2
N20459907: C53.2 R49.2 U11.4
N20481050: C69.2 C70.1 D18.C U15.1 U15.3
N20505812: C73.1 J3.2
N20509362: TP4.1(TP) U3.12
N20509364: TP5.1(TP) U3.11
N20509368: TP6.1(TP) U3.10
N20509433: TP8.1(TP) U3.13
N20509448: TP7.1(TP) U3.14
N20509463: TP9.1(TP) U3.15
N20509471: TP10.1(TP) U3.16
N20509473: R136.1 U3.5
N20509515: R137.1 U3.4
N202577100: J10.2 R21.1
N202577180: J10.4 R20.1
N204580687: R24.1 U9.8
N204596791: R42.2 U11.8
N204596931: R43.2 U10.2
N204597071: R44.2 U11.2
N204597510: R45.1 R51.1
N204597660: R46.1 R52.1
N204598021: J23.1 R48.1
N204598461: J24.1 R50.1
N204598551: D11.C R50.2
N205078799: J9.9 R135.1

Pads without a net: J2 4; J3 4; J4 4; J6 10; J7 9 11; J8 A8 B8; J9 10; J29 2; NOREF 1; NOREF#2 1; NOREF#3 1; NOREF#4 1; U12 4; U13 6; U14 1 5 8; U15 4

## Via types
v1: diameter 0.5, hole 0.3, TOP to BOTTOM, 1304 vias

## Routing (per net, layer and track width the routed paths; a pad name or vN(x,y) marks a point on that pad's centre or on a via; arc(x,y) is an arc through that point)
12V: length 43.2
  POWER w0.5: S1.2 S1.5 ; v1(6.99,34.06) 5.59,35.46 v1(3.99,35.46)
  BOTTOM w0.5: S1.5 32.21,26.36 19.99,26.36 14.49,31.86 12.19,31.86 9.99,34.06 v1(6.99,34.06) ; v1(3.99,35.46) 3.99,38.96 2.49,40.46 2.1,40.46
GND: length 261.3
  TOP w0.2: 22.49,17.76 21.39,16.66 21.39,12.61 v1(20.94,12.16) ; 29.69,12.46 29.69,16.66 28.69,17.66 ; 18.89,12.26 18.89,16.76 19.99,17.86 ; v1(31.88,12.23) 32.19,12.54 32.19,17.26 ; U8.2 21.8,46.14 21.8,46.14 v1(21.8,46.23) ; J8.15 61.21,2.44 v1(61.49,2.16) ; 34.59,26.56 34.49,26.46 32.59,26.46 ; 3.59,78.46 5.69,78.46 6.09,78.06 ; v1(65.89,11.18) 65.89,11.18 65.69,10.98 D2.1 ; 6.09,78.06 6.09,81.46 ; 6.09,78.06 v1(6.3,77.85) ; 32.59,28.96 34.49,28.96 34.59,28.86 ; 35.59,28.86 37.79,28.86 38.09,28.56 ; 19.29,85.36 21.1,85.36 v1(21.14,85.32) ; R13.1 63.13,10.43 D1.1 63.13,11.16 v1(62.91,11.16) ; 35.49,76.56 35.19,76.26 ; 5.39,68.16 6.09,68.86 6.09,70.86 ; J8.14 70.34,5.18 70.7,5.18 70.99,5.47 71.38,5.47 71.66,5.75 71.66,6.13 71.45,6.34 71.65,6.34 v1(71.86,6.13) ; 6.09,70.86 6.09,73.16 ; 6.09,70.86 3.69,70.86 ; 6.09,70.86 8.49,70.86 ; 3.69,75.96 5.99,75.96 ; 11.49,85.46 13.99,85.46 ; v1(40.73,69.06) 40.7,69.09 40.03,69.09 ; 35.99,26.56 37.79,26.56 ; 3.69,73.36 5.99,73.36 ; 42.56,72.69 v1(42.46,72.59)
  TOP w0.5: 40.17,80.31 44.1,80.31 v1(44.6,79.81) v1(44.6,75.8) 44.26,75.45 v1(40.73,75.45) v1(39.94,75.45) v1(39.4,76) v1(39.4,76.8) ; 40.17,80.31 v1(40.02,80.16) C9.1 ; 40.17,80.31 39.89,80.31 39.39,79.81 v1(39.39,79.27)
  GND w0.2: 34.59,14.76 34.48,14.87 32.3,14.87 ; 29.69,14.87 29.69,17.16 ; 29.69,14.87 v1(27.33,14.87) ; 29.69,14.87 29.69,12.16 ; 29.69,14.87 32.29,14.87 ; 3.49,70.96 6.09,70.96 ; 6.09,70.96 8.59,70.96 8.69,70.86 ; 6.09,70.96 6.09,73.16 ; 6.09,70.96 6.09,68.76 5.49,68.16 ; 32.69,26.46 34.29,26.46 ; 21.49,14.86 23.89,14.86 ; 21.49,14.86 21.49,17.16 ; 21.49,14.86 18.89,14.86 ; 21.49,14.86 21.49,12.46 ; 32.59,29.06 34.39,29.06 ; 32.35,12.26 32.35,12.42 32.29,12.48 32.29,14.86 ; 6.09,81.06 6.09,78.66 5.99,78.56 ; 32.3,14.87 32.29,14.87 ; 32.3,14.87 32.29,14.86 ; 32.29,14.87 32.29,14.86 ; 32.29,14.87 32.29,17.16 ; 6.09,75.86 5.99,75.96 3.59,75.96 ; v1(21.14,85.32) 21.1,85.36 19.29,85.36 ; 18.89,14.86 16.59,14.86 ; 18.89,14.86 18.89,12.56 ; 18.89,14.86 18.89,17.06 ; 35.99,26.46 37.89,26.46 ; 5.99,78.56 6.19,78.56 ; 5.99,78.56 3.69,78.56 ; 36.09,28.96 37.79,28.96 ; 3.79,73.36 5.99,73.36
  POWER w0.2: 27.19,17.26 27.21,17.28 29.27,17.28 ; 35.99,26.46 37.99,26.46 ; 29.69,12.26 29.69,16.86 29.27,17.28 ; 5.99,80.86 5.99,78.66 5.89,78.56 3.59,78.56 ; 32.39,29.06 34.49,29.06 34.59,28.96 ; 18.89,17.16 18.89,12.46 ; 29.27,17.28 31.47,17.28 32.19,16.56 32.19,12.58 ; 5.39,67.96 5.99,68.56 5.99,70.36 5.49,70.86 3.79,70.86 ; 35.99,29.06 37.79,29.06 37.89,28.96 ; 3.69,76.06 5.99,76.06 6.09,75.96 ; 32.69,26.46 34.62,26.46
  BOTTOM w0.2: 27.99,30.16 27.99,27.26 ; 27.99,30.16 27.99,32.76 ; 27.99,30.16 25.19,30.16 ; 27.99,30.16 30.62,30.16 v1(30.95,30.49) ; 40.39,24.26 43.89,24.26 ; 27.99,32.76 25.69,32.76 ; 27.99,32.76 30.29,32.76 30.49,32.56 ; 21.49,17.16 21.49,12.71 v1(20.94,12.16) ; v1(31.88,12.23) 32.19,12.54 32.19,17.06 ; 24.29,30.16 24.19,30.26 18.29,30.26 ; 18.69,32.76 20.99,32.76 ; 6.23,75.02 5.29,75.96 3.69,75.96 ; 3.69,70.86 5.39,70.86 6.09,70.16 6.09,68.86 5.39,68.16 ; 3.59,78.46 5.29,78.46 5.79,77.96 6.19,77.96 v1(6.3,77.85) ; 35.49,28.86 37.99,28.86 38.09,28.76 ; 46.89,24.16 50.09,24.16 ; 29.49,12.26 29.79,12.56 29.79,17.16 ; 21.49,32.76 23.69,32.76 ; 77.36,77.24 77.36,79.61 ; 35.99,26.46 37.89,26.46 ; 32.59,28.96 34.39,28.96 ; 18.99,12.46 18.89,12.56 18.89,17.16
  vias: v1(0.55,86.15) v1(0.55,84.15) v1(0.55,82.15) v1(0.55,80.15) v1(0.55,78.15) v1(0.55,76.15) v1(0.55,74.15) v1(0.55,72.15) v1(0.55,70.15) v1(0.55,68.15) v1(0.56,66.22) v1(0.55,63.7) v1(0.59,62.03) v1(0.58,59.49) v1(0.55,56.97) v1(0.58,54.3) v1(0.55,51.94) v1(0.63,49.3) v1(0.55,46.97) v1(0.56,44.05) v1(0.59,41.46) v1(0.57,38.93) v1(0.59,36.83) v1(0.62,34.21) v1(0.58,31.62) v1(0.64,28.96) v1(0.59,26.77) v1(0.59,23.75) v1(0.58,21.37) v1(0.55,18.52) v1(0.62,16.27) v1(0.55,13.44) v1(0.55,10.86) v1(0.55,8.86) v1(0.55,6.86) v1(0.55,4.86) v1(0.55,2.86) v1(0.83,88.13) v1(1.14,44.28) v1(1.25,23.97) v1(1.27,13.82) v1(1.38,11.21) v1(1.48,1.08) v1(2.81,74.03) v1(2.77,70.71) v1(2.77,67.51) v1(3,89.45) v1(2.99,26.56) v1(2.99,23.96) v1(3.13,79.5) v1(3.13,77.5) v1(3.22,71.56) v1(3.33,81.5) v1(3.33,75.51) v1(3.39,63.66) v1(3.39,28.96) v1(3.39,18.86) v1(3.4,0.55) v1(3.59,83.48) v1(3.59,21.68) v1(3.64,21.1) v1(3.89,56.14) v1(4.03,34.24) v1(3.99,26.36) v1(4.28,16.16) v1(4.39,20.96) v1(4.79,9.46) v1(5,89.45) v1(4.99,67.26) v1(5.09,4.46) v1(5.19,5.36) v1(5.4,0.55) v1(5.52,85.02) v1(6.22,11.57) v1(6.22,9.57) v1(6.22,7.57) v1(6.41,5.58) v1(6.41,0.64) v1(6.59,14.46) v1(7,89.45) v1(7.19,4.46) v1(7.21,3.51) v1(7.4,0.55) v1(7.52,44.24) v1(7.58,46.73) v1(7.57,36.65) v1(7.84,84.15) v1(8.09,31.56) v1(8.09,28.96) v1(8.09,21.46) v1(8.09,3.33) v1(8.19,51.86) v1(8.19,13.86) v1(8.25,0.7) v1(8.86,2.96) v1(9,89.45) v1(8.96,82.53) v1(8.99,80.66) v1(9.1,76.84) v1(9.11,75.42) v1(9.19,74.06) v1(9.21,46.91) v1(9.18,36.68) v1(9.19,7.36) v1(9.25,44.31) v1(9.4,0.55) v1(9.79,10.26) v1(10.09,80.46) v1(10.26,0.61) v1(10.39,18.06) v1(10.36,16.25) v1(10.49,72.66) v1(10.66,5.22) v1(10.86,36.23) v1(10.89,23.36) v1(11,89.45) v1(11.12,87.14) v1(11.09,85.14) v1(11.05,83.14) v1(11.29,37.06) v1(11.36,29.19) v1(11.4,0.55) v1(11.69,74.36) v1(11.69,36.46) v1(11.77,14.84) v1(12.19,77.76) v1(12.29,39.66) v1(12.59,19.66) v1(12.77,13.1) v1(12.77,11.1) v1(12.77,9.1) v1(12.77,7.1) v1(12.77,5.1) v1(12.84,88.15) v1(12.93,3.11) v1(13,89.45) v1(12.96,82.52) v1(13.29,16.56) v1(13.4,0.55) v1(13.59,13.36) v1(13.89,26.76) v1(13.99,29.06) v1(13.98,3.58) v1(14.14,86.62) v1(14.19,76.86) v1(14.27,84.63) v1(14.63,22.49) v1(14.69,83.53) v1(14.69,19.66) v1(14.83,4.59) v1(15,89.45) v1(15.04,3.11) v1(15.4,0.55) v1(15.99,21.76) v1(15.95,13.58) v1(15.99,6.22) v1(16.05,15.58) v1(16.27,84.63) v1(16.29,78.76) v1(16.49,24.06) v1(16.64,17.49) v1(16.64,83.09) v1(17,89.45) v1(17.05,11.91) v1(17.05,9.91) v1(17.05,7.91) v1(17.29,32.36) v1(17.29,30.46) v1(17.39,35.06) v1(17.4,0.55) v1(17.59,37.96) v1(17.59,36.06) v1(17.69,45.26) v1(17.79,49.63) v1(17.86,83.42) v1(17.89,44.36) v1(17.86,3.22) v1(17.99,57.06) v1(18.09,80.86) v1(18.09,19.66) v1(18.19,25.76) v1(18.2,23.46) v1(18.16,11.16) v1(18.16,9.16) v1(18.16,7.16) v1(18.32,5.17) v1(18.59,17.92) v1(18.68,86.33) v1(18.67,84.33) v1(19,89.45) v1(19,3.11) v1(19.06,49.35) v1(19.39,58.66) v1(19.41,42.81) v1(19.4,0.55) v1(19.48,23.25) v1(19.62,63.03) v1(19.59,38.06) v1(19.59,9.77) v1(19.59,7.77) v1(19.66,88.07) v1(19.69,82.61) v1(19.7,5.78) v1(19.74,64.23) v1(19.99,35.46) v1(20.06,3.81) v1(20.39,65.96) v1(20.47,22.62) v1(20.56,50.74) v1(20.59,49.33) v1(20.55,43.61) v1(20.7,10.17) v1(20.7,8.17) v1(21,89.45) v1(20.99,6.2) v1(21.19,37.96) v1(21.21,23.49) v1(21.42,49.35) v1(21.4,0.55) v1(21.6,87.58) v1(21.64,57.87) v1(21.63,55.94) v1(21.79,64.56) v1(21.79,35.46) v1(21.86,22.77) v1(22.39,41.8) v1(22.59,63.05) v1(22.93,11.96) v1(23,89.45) v1(22.95,86.16) v1(22.98,84.53) v1(22.96,5.84) v1(23.39,59.62) v1(23.36,41.82) v1(23.39,3.88) v1(23.4,0.55) v1(23.54,88.07) v1(23.79,42.76) v1(23.97,38.86) v1(24.01,30.74) v1(24.14,15.36) v1(24.21,28.75) v1(24.21,24.75) v1(24.21,22.75) v1(24.29,37.86) v1(24.29,35.46) v1(24.34,13.37) v1(24.38,41.64) v1(24.49,43.2) v1(24.5,31.95) v1(24.79,62.84) v1(24.79,17.06) v1(24.79,14.76) v1(24.89,71.06) v1(24.86,53.15) v1(24.86,49.42) v1(24.92,43.78) v1(24.93,28.37) v1(24.93,24.37) v1(24.93,22.37) v1(25,89.45) v1(24.98,45.27) v1(24.95,30.37) v1(24.99,7.96) v1(25.05,58.66) v1(25.18,88.16) v1(25.27,4.31) v1(25.33,3.1) v1(25.4,0.55) v1(25.46,48.93) v1(25.49,11.36) v1(25.75,86.81) v1(26.15,6.1) v1(26.39,38.16) v1(26.39,35.76) v1(26.52,53.38) v1(26.74,43.96) v1(26.92,84.7) v1(26.9,16.82) v1(26.89,12.92) v1(27,89.45) v1(26.99,55.76) v1(27.19,88.16) v1(27.19,41.86) v1(27.27,22.6) v1(27.4,0.55) v1(27.75,86.81) v1(27.91,23.47) v1(27.85,11.16) v1(27.85,9.16) v1(27.85,7.16) v1(28.02,53.08) v1(28.09,55.76) v1(28.19,42.46) v1(28.48,3.43) v1(28.55,22.74) v1(28.73,49.35) v1(28.71,5.42) v1(28.92,84.7) v1(28.89,43.76) v1(29,89.45) v1(28.95,11.4) v1(28.95,9.4) v1(28.95,7.4) v1(29.19,88.16) v1(29.15,46.67) v1(29.41,54.22) v1(29.41,51.34) v1(29.39,35.76) v1(29.4,0.55) v1(29.49,41.08) v1(29.69,48.91) v1(29.75,86.81) v1(29.79,55.83) v1(30.12,48.34) v1(30.18,51.02) v1(30.16,47.49) v1(30.18,46.5) v1(30.19,42.16) v1(30.28,75.75) v1(30.34,73.53) v1(30.39,71.96) v1(30.39,10.02) v1(30.39,8.02) v1(30.39,6.02) v1(30.41,4.02) v1(30.47,3.13) v1(30.6,52.99) v1(30.66,38.98) v1(30.92,84.7) v1(30.92,31.33) v1(31,89.45) v1(30.97,25.33) v1(30.97,23.33) v1(31.14,58.59) v1(31.19,88.16) v1(31.29,52.96) v1(31.4,0.55) v1(31.52,32.07) v1(31.49,10.27) v1(31.49,8.27) v1(31.59,65.26) v1(31.63,54.27) v1(31.63,6.27) v1(31.75,86.81) v1(31.77,51.31) v1(31.77,49.61) v1(31.8,47.2) v1(31.8,46.14) v1(31.78,45.27) v1(31.89,31.31) v1(31.99,38.56) v1(32.04,24.92) v1(32.29,36.26) v1(32.39,75.69) v1(32.39,73.48) v1(32.39,71.96) v1(32.45,82.91) v1(32.82,45.27) v1(32.92,84.7) v1(32.89,52.86) v1(32.86,23.09) v1(33.12,83.04) v1(33.09,17.86) v1(33.19,38.26) v1(33.4,0.55) v1(33.54,5.67) v1(33.59,65.46) v1(33.72,3.68) v1(33.9,82.23) v1(33.86,11.94) v1(34.01,32.11) v1(34.28,73.46) v1(34.29,71.96) v1(34.26,23.4) v1(34.34,75.69) v1(34.59,85.28) v1(34.63,83.66) v1(34.71,84.58) v1(34.68,82.77) v1(34.69,36.16) v1(34.74,81.67) v1(34.87,80.83) v1(35.09,62.16) v1(35.09,26.49) v1(35.11,24.25) v1(35.08,15.32) v1(35.13,13.48) v1(35.22,42.6) v1(35.19,29.21) v1(35.28,41.63) v1(35.39,85.36) v1(35.37,84.53) v1(35.35,83.56) v1(35.35,82.41) v1(35.35,81.48) v1(35.41,80.39) v1(35.39,79.56) v1(35.39,78.66) v1(35.4,38.8) v1(35.4,0.55) v1(35.62,26.15) v1(35.73,23.69) v1(35.79,9.86) v1(35.79,5.06) v1(35.99,76.66) v1(36.17,42.53) v1(36.23,41.67) v1(36.29,67.66) v1(36.59,62.26) v1(36.93,32.11) v1(37.11,77.4) v1(37.19,83.16) v1(37.19,82.16) v1(37.19,37.66) v1(37.3,80.42) v1(37.29,79.42) v1(37.31,4.54) v1(37.38,15.02) v1(37.44,13.03) v1(37.4,0.55) v1(37.45,3.1) v1(37.57,23.35) v1(37.57,21.35) v1(37.79,53.56) v1(37.94,84.06) v1(37.89,83.17) v1(37.91,82.21) v1(37.94,81.16) v1(37.92,80.29) v1(37.91,79.43) v1(37.86,78.62) v1(37.89,17.86) v1(37.99,84.86) v1(37.98,67.36) v1(38.2,6.3) v1(38.39,55.86) v1(38.36,29.16) v1(38.48,57.09) v1(38.46,27.15) v1(38.58,58.59) v1(38.71,47.2) v1(38.81,82.92) v1(38.8,80.78) v1(38.75,75.84) v1(39.09,37.46) v1(39.23,29.22) v1(39.31,64.76) v1(39.33,25.74) v1(39.4,0.55) v1(39.49,17.86) v1(39.63,84.12) v1(39.59,39.06) v1(39.69,39.76) v1(39.74,72.21) v1(39.81,45.54) v1(40.02,24.46) v1(39.99,22.46) v1(40.16,28.45) v1(40.17,26.45) v1(40.25,41.58) v1(40.31,29.26) v1(40.38,5.83) v1(40.48,57.09) v1(40.49,53.56) v1(40.49,35.66) v1(40.49,31.16) v1(40.49,12.56) v1(40.55,81.76) v1(40.58,58.59) v1(40.64,40.38) v1(40.59,37.56) v1(40.69,62.36) v1(40.66,15.14) v1(40.81,82.92) v1(40.8,80.31) v1(40.78,3.87) v1(41.09,50.76) v1(41.29,21.16) v1(41.4,0.55) v1(41.48,27.4) v1(41.56,86.65) v1(41.63,84.12) v1(41.59,65.46) v1(41.67,88.08) v1(41.88,80.31) v1(41.89,75.47) v1(41.87,42.46) v1(41.89,20.66) v1(41.99,68.36) v1(41.99,37.56) v1(41.99,35.66) v1(42.1,89.45) v1(42.19,53.56) v1(42.33,27.42) v1(42.47,57.09) v1(42.49,55.76) v1(42.55,81.76) v1(42.57,58.59) v1(42.59,12.56) v1(42.59,2.96) v1(42.66,15.25) v1(42.81,82.92) v1(42.79,64.96) v1(42.79,33.66) v1(42.79,8.26) v1(42.87,49.99) v1(43.09,5.96) v1(43.2,80.31) v1(43.28,75.42) v1(43.33,40.96) v1(43.29,37.56) v1(43.29,35.66) v1(43.4,0.55) v1(43.44,11.51) v1(43.56,86.65) v1(43.63,84.12) v1(43.67,88.08) v1(43.99,62.36) v1(43.99,53.46) v1(43.95,27.27) v1(44.1,89.45) v1(44.16,75.42) v1(44.43,80.65) v1(44.39,65.06) v1(44.49,37.56) v1(44.55,81.76) v1(44.59,78.78) v1(44.6,77.61) v1(44.62,76.68) v1(44.57,58.59) v1(44.59,35.66) v1(44.59,24.81) v1(44.66,56.05) v1(44.81,82.92) v1(44.75,11.59) v1(44.89,50.88) v1(44.87,49.3) v1(44.89,47.62) v1(44.89,34.06) v1(45.24,21.12) v1(45.4,0.55) v1(45.53,46.7) v1(45.56,86.65) v1(45.63,84.12) v1(45.59,23.08) v1(45.59,14.86) v1(45.67,88.08) v1(45.74,13.33) v1(45.78,76.73) v1(45.84,68.05) v1(45.87,39.47) v1(46.1,89.45) v1(46.09,40.96) v1(46.09,5.86) v1(46.33,27.81) v1(46.43,80.65) v1(46.39,53.76) v1(46.49,40.06) v1(46.47,23.85) v1(46.47,21.85) v1(46.49,20.56) v1(46.55,81.76) v1(46.57,58.59) v1(46.57,57.8) v1(46.63,9.85) v1(46.69,37.46) v1(46.81,82.92) v1(46.79,62.36) v1(46.83,25.81) v1(46.99,78.26) v1(46.99,44.74) v1(47.03,42.27) v1(47.1,11.86) v1(47.22,40.02) v1(47.25,31.31) v1(47.39,34.16) v1(47.4,0.55) v1(47.56,86.65) v1(47.63,84.12) v1(47.56,5.12) v1(47.67,88.08) v1(47.84,68.05) v1(47.84,66.05) v1(47.82,65.04) v1(48.02,75.25) v1(47.97,27.54) v1(47.99,8.36) v1(48.1,89.45) v1(48.07,75.68) v1(48.08,3.19) v1(48.43,80.65) v1(48.39,78.66) v1(48.55,81.76) v1(48.57,58.59) v1(48.57,57.8) v1(48.59,35.66) v1(48.69,32.86) v1(48.81,82.92) v1(48.77,55.42) v1(48.81,27.55) v1(48.93,14.77) v1(48.88,12.77) v1(48.94,44.71) v1(49.04,16.77) v1(49.29,52.76) v1(49.4,0.55) v1(49.56,86.65) v1(49.63,84.12) v1(49.67,88.08) v1(49.69,34.16) v1(49.84,68.05) v1(49.84,66.05) v1(49.81,39.89) v1(49.88,41.65) v1(50.1,89.45) v1(50.13,82.98) v1(50.23,81.53) v1(50.19,24.7) v1(50.29,62.36) v1(50.29,17.28) v1(50.39,6.16) v1(50.5,27.47) v1(50.57,58.59) v1(50.57,57.8) v1(50.81,13.39) v1(50.78,3.02) v1(50.99,32.86) v1(50.94,15.39) v1(51.08,39.89) v1(51.09,38.86) v1(51.09,7.86) v1(51.07,4.65) v1(51.17,75.22) v1(51.24,23) v1(51.39,76.26) v1(51.4,0.55) v1(51.49,73.26) v1(51.59,10.56) v1(51.69,56.56) v1(51.66,44.97) v1(51.84,68.05) v1(51.84,66.05) v1(51.8,21.08) v1(51.89,52.69) v1(52.1,89.45) v1(52.19,34.96) v1(52.27,84.53) v1(52.29,27.06) v1(52.27,5.71) v1(52.69,31.16) v1(52.72,3.76) v1(52.68,2.93) v1(52.78,81.6) v1(52.89,73.16) v1(52.89,17.62) v1(53.1,83.85) v1(53.09,62.26) v1(53.19,58.56) v1(53.19,28.26) v1(53.27,40.83) v1(53.27,38.93) v1(53.35,84.85) v1(53.37,50.01) v1(53.4,46.98) v1(53.4,0.55) v1(53.45,48.45) v1(53.49,33.66) v1(53.59,6.22) v1(53.65,82.94) v1(53.77,79.71) v1(53.84,68.05) v1(53.84,66.05) v1(53.92,76.78) v1(54.1,89.45) v1(54.11,41.83) v1(54.29,14.86) v1(54.43,41.01) v1(54.41,16.29) v1(54.49,62.88) v1(54.49,27.06) v1(54.5,13.69) v1(54.59,9.26) v1(54.69,78.76) v1(54.69,57.06) v1(54.78,81.6) v1(54.8,44.57) v1(54.89,29.06) v1(55.09,58.96) v1(55.23,84.17) v1(55.39,71.66) v1(55.4,0.55) v1(55.56,5.88) v1(55.8,80.08) v1(55.84,68.05) v1(55.84,66.05) v1(55.79,31.46) v1(55.83,14.87) v1(55.9,14.22) v1(55.89,13.56) v1(56.1,89.45) v1(56.05,3.94) v1(56.19,52.86) v1(56.32,83.9) v1(56.34,11.21) v1(56.47,86.27) v1(56.6,76.78) v1(56.57,59.8) v1(56.57,57.8) v1(56.72,17.22) v1(56.78,81.6) v1(56.79,73.26) v1(56.89,24.56) v1(57.01,46.01) v1(56.99,26.96) v1(57.09,78.86) v1(57.11,41.42) v1(57.29,70.96) v1(57.38,88.15) v1(57.4,0.55) v1(57.49,29.76) v1(57.71,51.18) v1(57.77,79.71) v1(57.84,68.05) v1(57.84,66.05) v1(57.89,1.86) v1(58.02,42.67) v1(57.99,18.66) v1(57.99,17.16) v1(58.1,89.45) v1(58.07,74.44) v1(58.32,83.9) v1(58.29,61.86) v1(58.59,72.36) v1(58.59,15.46) v1(58.82,48.19) v1(58.99,70.26) v1(59.1,46.5) v1(59.09,22.46) v1(59.13,4.71) v1(59.19,49.75) v1(59.29,27.96) v1(59.39,24.46) v1(59.4,0.55) v1(59.49,75.46) v1(59.55,19.05) v1(59.98,42.23) v1(60.1,89.45) v1(60.09,36.06) v1(60.19,4.76) v1(60.41,39.72) v1(60.41,37.68) v1(60.41,34.64) v1(60.41,32.6) v1(60.42,17.22) v1(60.79,23.16) v1(60.99,78.66) v1(61.19,13.46) v1(61.29,10.26) v1(61.42,18.29) v1(61.42,15.49) v1(61.4,0.55) v1(61.49,25.66) v1(61.59,3.6) v1(61.71,41.24) v1(61.69,12.96) v1(61.77,79.71) v1(61.89,58.86) v1(61.89,35.96) v1(61.89,30.96) v1(61.97,84.69) v1(61.99,74.06) v1(61.99,71.56) v1(61.99,64.06) v1(61.99,56.36) v1(61.99,53.66) v1(61.99,28.36) v1(61.99,16.16) v1(61.99,10.26) v1(62.1,89.45) v1(62.09,66.46) v1(62.13,38.7) v1(62.13,33.62) v1(62.59,10.26) v1(62.92,16.29) v1(63.09,20.86) v1(63.04,18) v1(63.07,14.36) v1(63.4,0.55) v1(63.69,23.46) v1(64.11,89.45) v1(64.3,3.15) v1(64.69,22.46) v1(64.69,19.26) v1(64.99,13.16) v1(65.09,15.26) v1(65.19,16.26) v1(65.31,4.26) v1(65.4,0.55) v1(65.77,79.71) v1(66.01,44.12) v1(66.11,89.45) v1(66.19,20.96) v1(66.28,45.54) v1(66.27,43.17) v1(66.29,10.36) v1(66.56,66.68) v1(66.56,64.26) v1(66.56,52.03) v1(66.71,65.85) v1(66.7,2.49) v1(66.84,58.62) v1(66.85,9.44) v1(67.4,0.55) v1(67.62,9.41) v1(67.66,66.64) v1(67.66,3.64) v1(67.78,59.02) v1(68,51.18) v1(67.99,13.16) v1(68.11,89.45) v1(68.09,18.96) v1(68.09,16.66) v1(68.15,64.1) v1(68.15,61.56) v1(68.19,20.46) v1(68.29,30.96) v1(68.39,38.56) v1(68.39,33.46) v1(68.49,28.36) v1(68.51,23.09) v1(68.65,66.49) v1(68.8,58.83) v1(68.91,78.61) v1(68.99,63.88) v1(69.11,51.2) v1(69.14,61.38) v1(69.19,12.96) v1(69.19,4.66) v1(69.31,53.75) v1(69.39,56.26) v1(69.39,41.14) v1(69.4,0.55) v1(69.66,66.65) v1(69.76,85.04) v1(69.89,11.26) v1(70.01,64.83) v1(70.01,62.29) v1(70.11,89.45) v1(70.26,14.2) v1(70.63,60.88) v1(70.73,70.71) v1(70.7,6.52) v1(70.78,57.17) v1(70.77,55.67) v1(70.8,14.7) v1(70.92,54.06) v1(71.03,37.8) v1(71.06,58.91) v1(71.09,45.46) v1(71.09,2.26) v1(71.16,67.97) v1(71.19,5.94) v1(71.29,52.77) v1(71.3,42.35) v1(71.4,0.55) v1(71.68,15.49) v1(71.82,72.2) v1(71.8,54.64) v1(71.75,30.49) v1(72.01,42.78) v1(71.99,13.16) v1(72.11,89.45) v1(72.23,35.98) v1(72.25,41.71) v1(72.45,68.68) v1(72.58,69.38) v1(72.56,66.61) v1(72.61,64.88) v1(72.76,74.01) v1(72.96,77.64) v1(72.95,36.75) v1(73.05,67.58) v1(73.29,52.77) v1(73.4,64.11) v1(73.4,0.55) v1(73.67,82.43) v1(73.67,30.38) v1(73.83,29.88) v1(73.86,32.77) v1(73.99,70.8) v1(73.95,43.26) v1(74,35.94) v1(74.11,89.45) v1(74.23,79.19) v1(74.33,50.91) v1(74.33,25.51) v1(74.28,19.61) v1(74.34,44.86) v1(74.52,76.73) v1(74.48,62.18) v1(74.54,55.41) v1(74.6,60.19) v1(74.57,57.14) v1(74.7,9.39) v1(74.69,6.76) v1(75.21,34.31) v1(75.24,28.46) v1(75.4,0.55) v1(75.56,72.92) v1(75.59,11.66) v1(75.72,23.83) v1(75.69,5.96) v1(75.77,45.49) v1(75.92,71.32) v1(75.87,67.16) v1(75.89,49.02) v1(75.97,37.65) v1(76.04,25.33) v1(76.11,89.45) v1(76.11,69.41) v1(76.27,46.72) v1(76.29,11.66) v1(76.5,64.26) v1(76.52,55.31) v1(76.51,21.12) v1(76.58,82.42) v1(76.59,59.96) v1(76.55,57.12) v1(76.58,44.13) v1(76.66,42.19) v1(76.71,33.19) v1(76.66,27.05) v1(76.69,24.07) v1(76.81,45.84) v1(76.8,30.24) v1(76.93,49.97) v1(77.29,2.72) v1(77.4,0.55) v1(77.5,84.64) v1(77.83,72.43) v1(77.81,62.76) v1(77.92,71.32) v1(78.02,61.35) v1(78.11,89.45) v1(78.1,69.29) v1(78.22,67.29) v1(78.21,65.29) v1(78.36,45.87) v1(78.53,26.33) v1(78.72,40.66) v1(78.81,75.15) v1(78.81,27.96) v1(78.81,25.06) v1(78.94,46.92) v1(78.97,38.43) v1(79.03,34.66) v1(78.97,28.76) v1(79.09,68) v1(79.12,65.77) v1(79.16,52.45) v1(79.3,50.46) v1(79.29,48.89) v1(79.31,41.81) v1(79.32,37.26) v1(79.25,2.32) v1(79.39,11.56) v1(79.37,8.72) v1(79.39,5.86) v1(79.4,0.55) v1(79.52,12.46) v1(79.57,54.41) v1(79.59,6.66) v1(79.74,66.92) v1(79.69,4.28) v1(79.81,62.76) v1(79.81,48.11) v1(79.77,43.76) v1(79.8,35.33) v1(79.76,30.87) v1(79.92,71.32) v1(79.99,9.25) v1(80.11,89.45) v1(80.08,77.68) v1(80.19,6.76) v1(80.33,63.55) v1(80.29,32.68) v1(80.4,67.99) v1(80.36,45.5) v1(80.37,12.45) v1(80.51,65.74) v1(80.64,24.24) v1(80.7,50.3) v1(80.82,60.75) v1(80.92,41.63) v1(81.02,78.79) v1(81.09,7.56) v1(81.16,13.6) v1(81.33,82.44) v1(81.32,66.66) v1(81.3,64.66) v1(81.4,0.55) v1(81.54,54.11) v1(81.57,52.11) v1(81.56,39.73) v1(81.57,26.01) v1(81.69,43.21) v1(81.71,30.43) v1(81.78,58.64) v1(81.8,37.58) v1(81.92,71.34) v1(81.92,31.53) v1(81.92,27.96) v1(81.89,9.19) v1(81.98,75.72) v1(81.96,60.86) v1(81.97,44.32) v1(82.11,89.45) v1(82.08,77.68) v1(82.42,69.5) v1(83.19,3.76) v1(83.4,0.55) v1(83.49,2.72) v1(83.61,45.46) v1(83.63,41.95) v1(83.69,54.41) v1(83.67,28.79) v1(83.77,63.29) v1(83.74,59.04) v1(83.75,33.21) v1(83.79,25.96) v1(83.79,22.96) v1(83.9,55.78) v1(83.95,61.01) v1(84.11,89.45) v1(84.04,77.28) v1(84.2,63.98) v1(84.5,75.34) v1(84.55,69.83) v1(85.13,84.64) v1(85.18,73.58) v1(85.23,64.41) v1(85.22,20.48) v1(85.28,79.51) v1(85.44,41.81) v1(85.35,13.95) v1(85.44,6.23) v1(85.4,0.55) v1(85.5,62.28) v1(85.51,22.42) v1(85.53,15.54) v1(85.45,2.32) v1(85.6,77.54) v1(85.6,75.54) v1(85.59,45.71) v1(85.56,32.93) v1(85.74,8.62) v1(85.81,48.11) v1(85.8,35.33) v1(85.83,28.68) v1(85.82,21.84) v1(85.89,4.28) v1(86.01,82.02) v1(85.97,43.74) v1(85.96,30.97) v1(86.04,25.01) v1(85.97,17.5) v1(86.11,89.45) v1(86.11,53.36) v1(86.17,51.5) v1(86.19,40.39) v1(86.14,25.59) v1(86.46,39.11) v1(86.68,68.69) v1(86.94,32.24) v1(87.03,30.56) v1(87.11,43.17) v1(87.06,17.04) v1(87.19,44.72) v1(87.4,14.95) v1(87.4,0.58) v1(87.96,67.94) v1(88.09,89.19) v1(88.33,6.13) v1(88.82,65.5) v1(89.07,1.69) v1(89.36,87.65) v1(89.45,85.65) v1(89.45,83.65) v1(89.45,81.65) v1(89.45,79.65) v1(89.45,77.65) v1(89.45,75.65) v1(89.45,73.65) v1(89.45,71.65) v1(89.45,69.65) v1(89.45,67.65) v1(89.45,65.65) v1(89.45,63.65) v1(89.45,61.65) v1(89.45,59.65) v1(89.45,57.65) v1(89.45,55.65) v1(89.45,53.65) v1(89.45,51.65) v1(89.45,49.65) v1(89.45,47.65) v1(89.45,45.65) v1(89.45,43.65) v1(89.45,41.65) v1(89.45,39.65) v1(89.45,37.65) v1(89.45,35.65) v1(89.45,33.65) v1(89.45,31.65) v1(89.45,29.65) v1(89.45,27.65) v1(89.45,25.65) v1(89.45,23.65) v1(89.45,21.65) v1(89.45,19.65) v1(89.45,17.65) v1(89.45,15.65) v1(89.45,13.65) v1(89.45,11.65) v1(89.45,9.65) v1(89.45,7.65) v1(89.45,5.65) v1(89.45,3.65)
V3: length 11.6
  TOP w0.2: 34.94,39.75 35.5,40.31 U3.6
  TOP w0.35: v1(34.44,38.76) C38.1 34.94,39.75 ; C76.1 32.9,43.54 v1(33.31,43.12) 33.59,42.84 34.33,42.84
  BOTTOM w0.35: v1(34.44,38.76) 31.29,41.91 31.29,42.45 31.96,43.12 v1(33.31,43.12)
VBAT_3V3: length 94.9
  TOP w0.5: U15.5 C68.1 74.53,5.02 v1(66.29,13.26)
  BOTTOM w0.5: v1(66.29,13.26) 66.29,19.86 49.19,36.96 49.19,39.06 36.09,52.16 23.9,52.16 17.82,58.24 J29.4
VBUS_DCDC: length 105.6
  TOP w0.5: U13.5 58.13,12.82 C62.1 ; R54.1 58.09,11.84 C62.1 ; C62.1 58.59,11.38 58.12,10.91 v1(58.12,4.58) ; C62.1 58.71,12.35 59.91,13.55 59.91,13.69 L8.2
  POWER w0.5: v1(58.12,4.58) 55.77,2.23 4.26,2.23 2.1,4.39 v1(2.1,36.76)
  BOTTOM w0.5: v1(2.1,36.76) 2.1,36.77 2.1,37.92
VCC_3V3: length 85.2
  TOP w0.5: v1(65.49,17.96) 72.67,10.79 C61.1 74.76,10.77 U12.5
  BOTTOM w0.5: J29.10 10.23,50.62 25.89,34.96 50.09,34.96 65.49,19.56 v1(65.49,17.96)
VCC_12V: length 129.7
  TOP w0.5: v1(84.68,62.05) 84,62.05 84,62.06 D15.C 75.69,62.06 CD1.1 75.64,63.41 74.92,64.13 C67.1 74.92,65.71 74.91,65.72 C66.1 ; R58.1 74.91,67.58 C66.1 ; C66.1 75.69,66.48 75.89,66.28 U14.7 ; 33.56,25.23 36.87,25.23
  POWER w0.5: v1(84.68,62.05) 84.68,22.25 69.39,6.96 42.51,6.96 36.68,12.79 36.68,25.04 36.87,25.23
VDD_DMIC: length 32.3
  TOP w0.2: v1(36.67,55.18) U5.2 45.88,55.18 U5.6 ; U4.6 21.14,55.16 v1(30.74,55.16)
  TOP w0.5: U5.6 48.18,56.18 C35.1 49.73,56.18 R61.2 ; C36.1 18.81,56.19 U4.6
  BOTTOM w0.2: v1(36.67,55.18) 36.65,55.16 v1(30.74,55.16)
VDDF: length 6.3
  TOP w0.2: VDDF.1 38.46,68.39 C14.1 36.25,68.96 34.89,68.96 34.59,69.25 U1.27
AIN_LINEIN_N: length 10.9
  TOP w0.2: C73.2 71.92,29.64 J7.37
AIN_LINEIN_P: length 11.3
  TOP w0.2: J7.33 74.02,34.72 76.57,37.27 76.57,38.6 C26.2
AIN_MIC_N: length 11.3
  TOP w0.2: J7.35 67.81,32.18 66.67,33.33 66.67,35.5 67.25,36.08 69.57,36.08 70.35,36.86 70.35,38.66 C74.2
AIN_MIC_P: length 7.1
  TOP w0.2: J7.31 68.91,37.26 69.95,38.3 69.95,39.14 71.76,40.95 72.48,40.95 C21.2
CAN1_3V3: length 1.9
  TOP w0.4: U8.5 19.27,39.33 18.87,38.93 R64.2
CAN1_5V: length 4.6
  TOP w0.5: R68.2 22.34,47.81 C39.2 21.41,47.81 C40.2 20.54,47.79 U8.3
CAN2_3V3: length 1.9
  TOP w0.5: U9.5 26.09,39.43 25.59,38.93 R67.2
CAN2_5V: length 4.6
  TOP w0.5: 27.37,45.08 R69.2 28.2,47.82 28.23,47.84 C45.2 28.31,47.82 29.12,47.82 29.13,47.84 C44.2
